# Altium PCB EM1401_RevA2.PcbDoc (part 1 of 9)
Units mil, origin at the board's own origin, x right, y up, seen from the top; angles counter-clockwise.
Board outline 7800 x 5300 mil, 6 copper layers (Top Layer, MidLayer1, MidLayer2, MidLayer3, MidLayer4, Bottom Layer), stack 16.8 mil thick; 751 components, 531 nets, 2554 pads, 1388 vias.
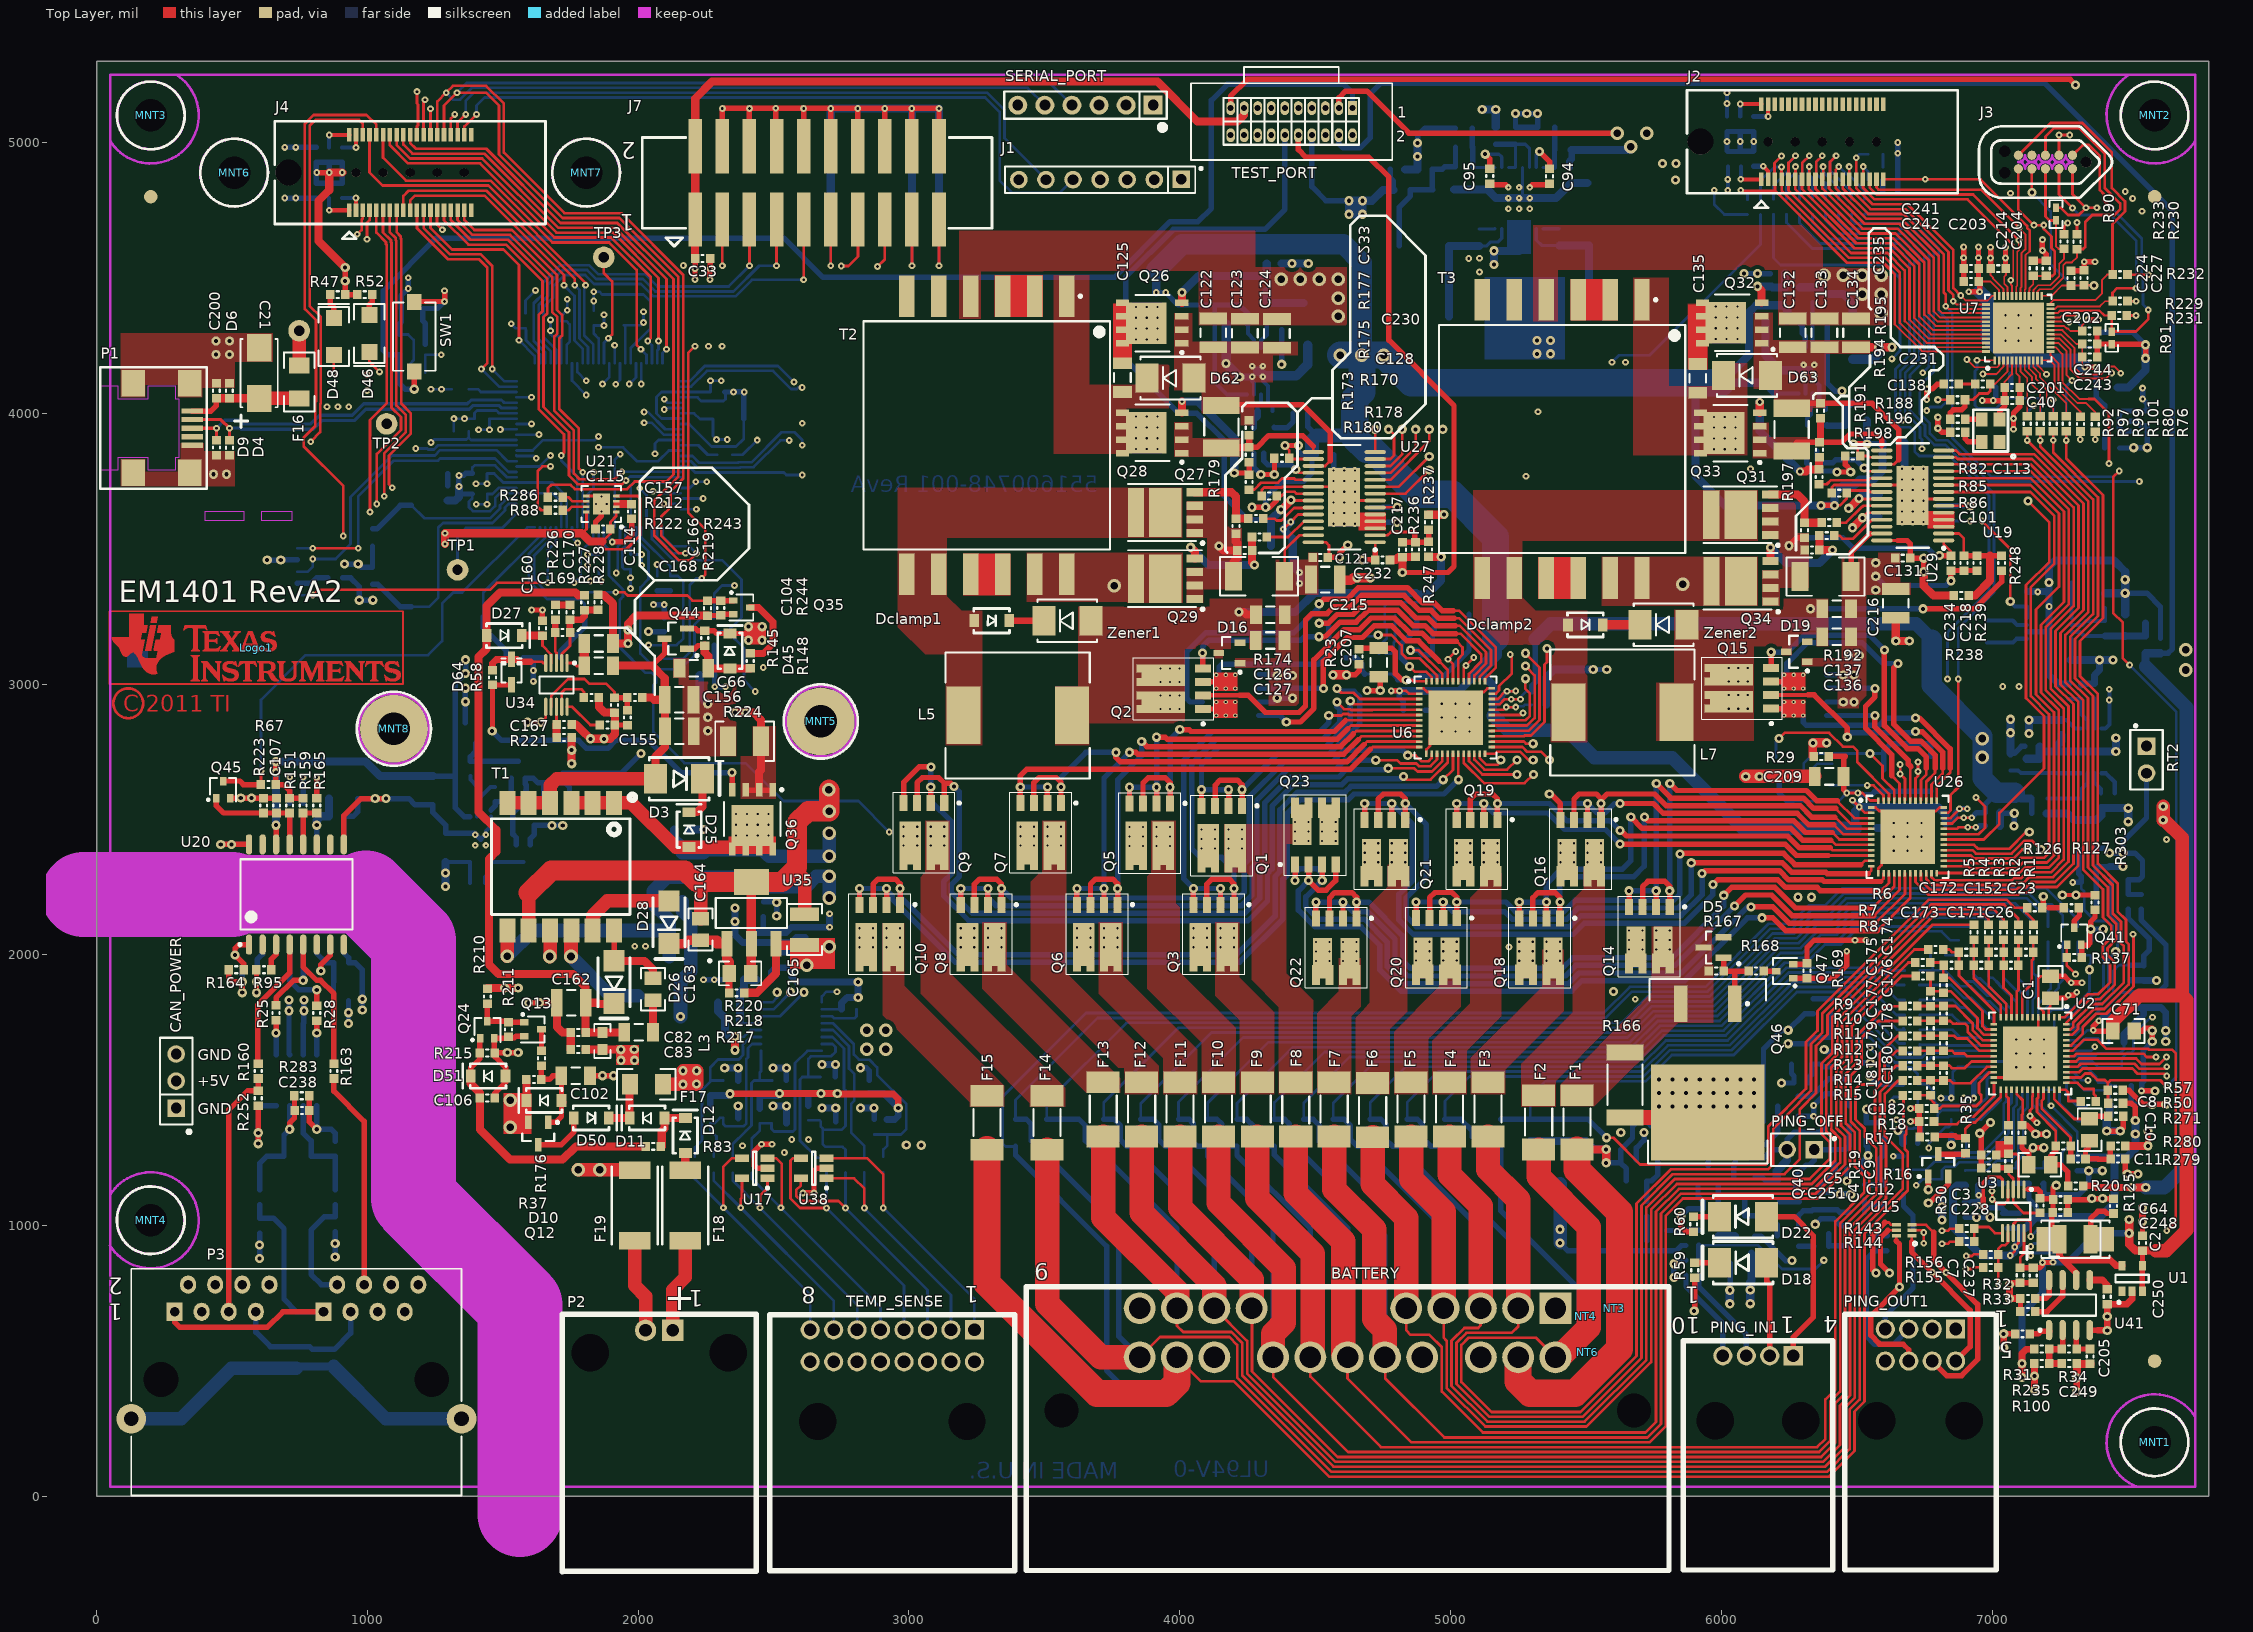
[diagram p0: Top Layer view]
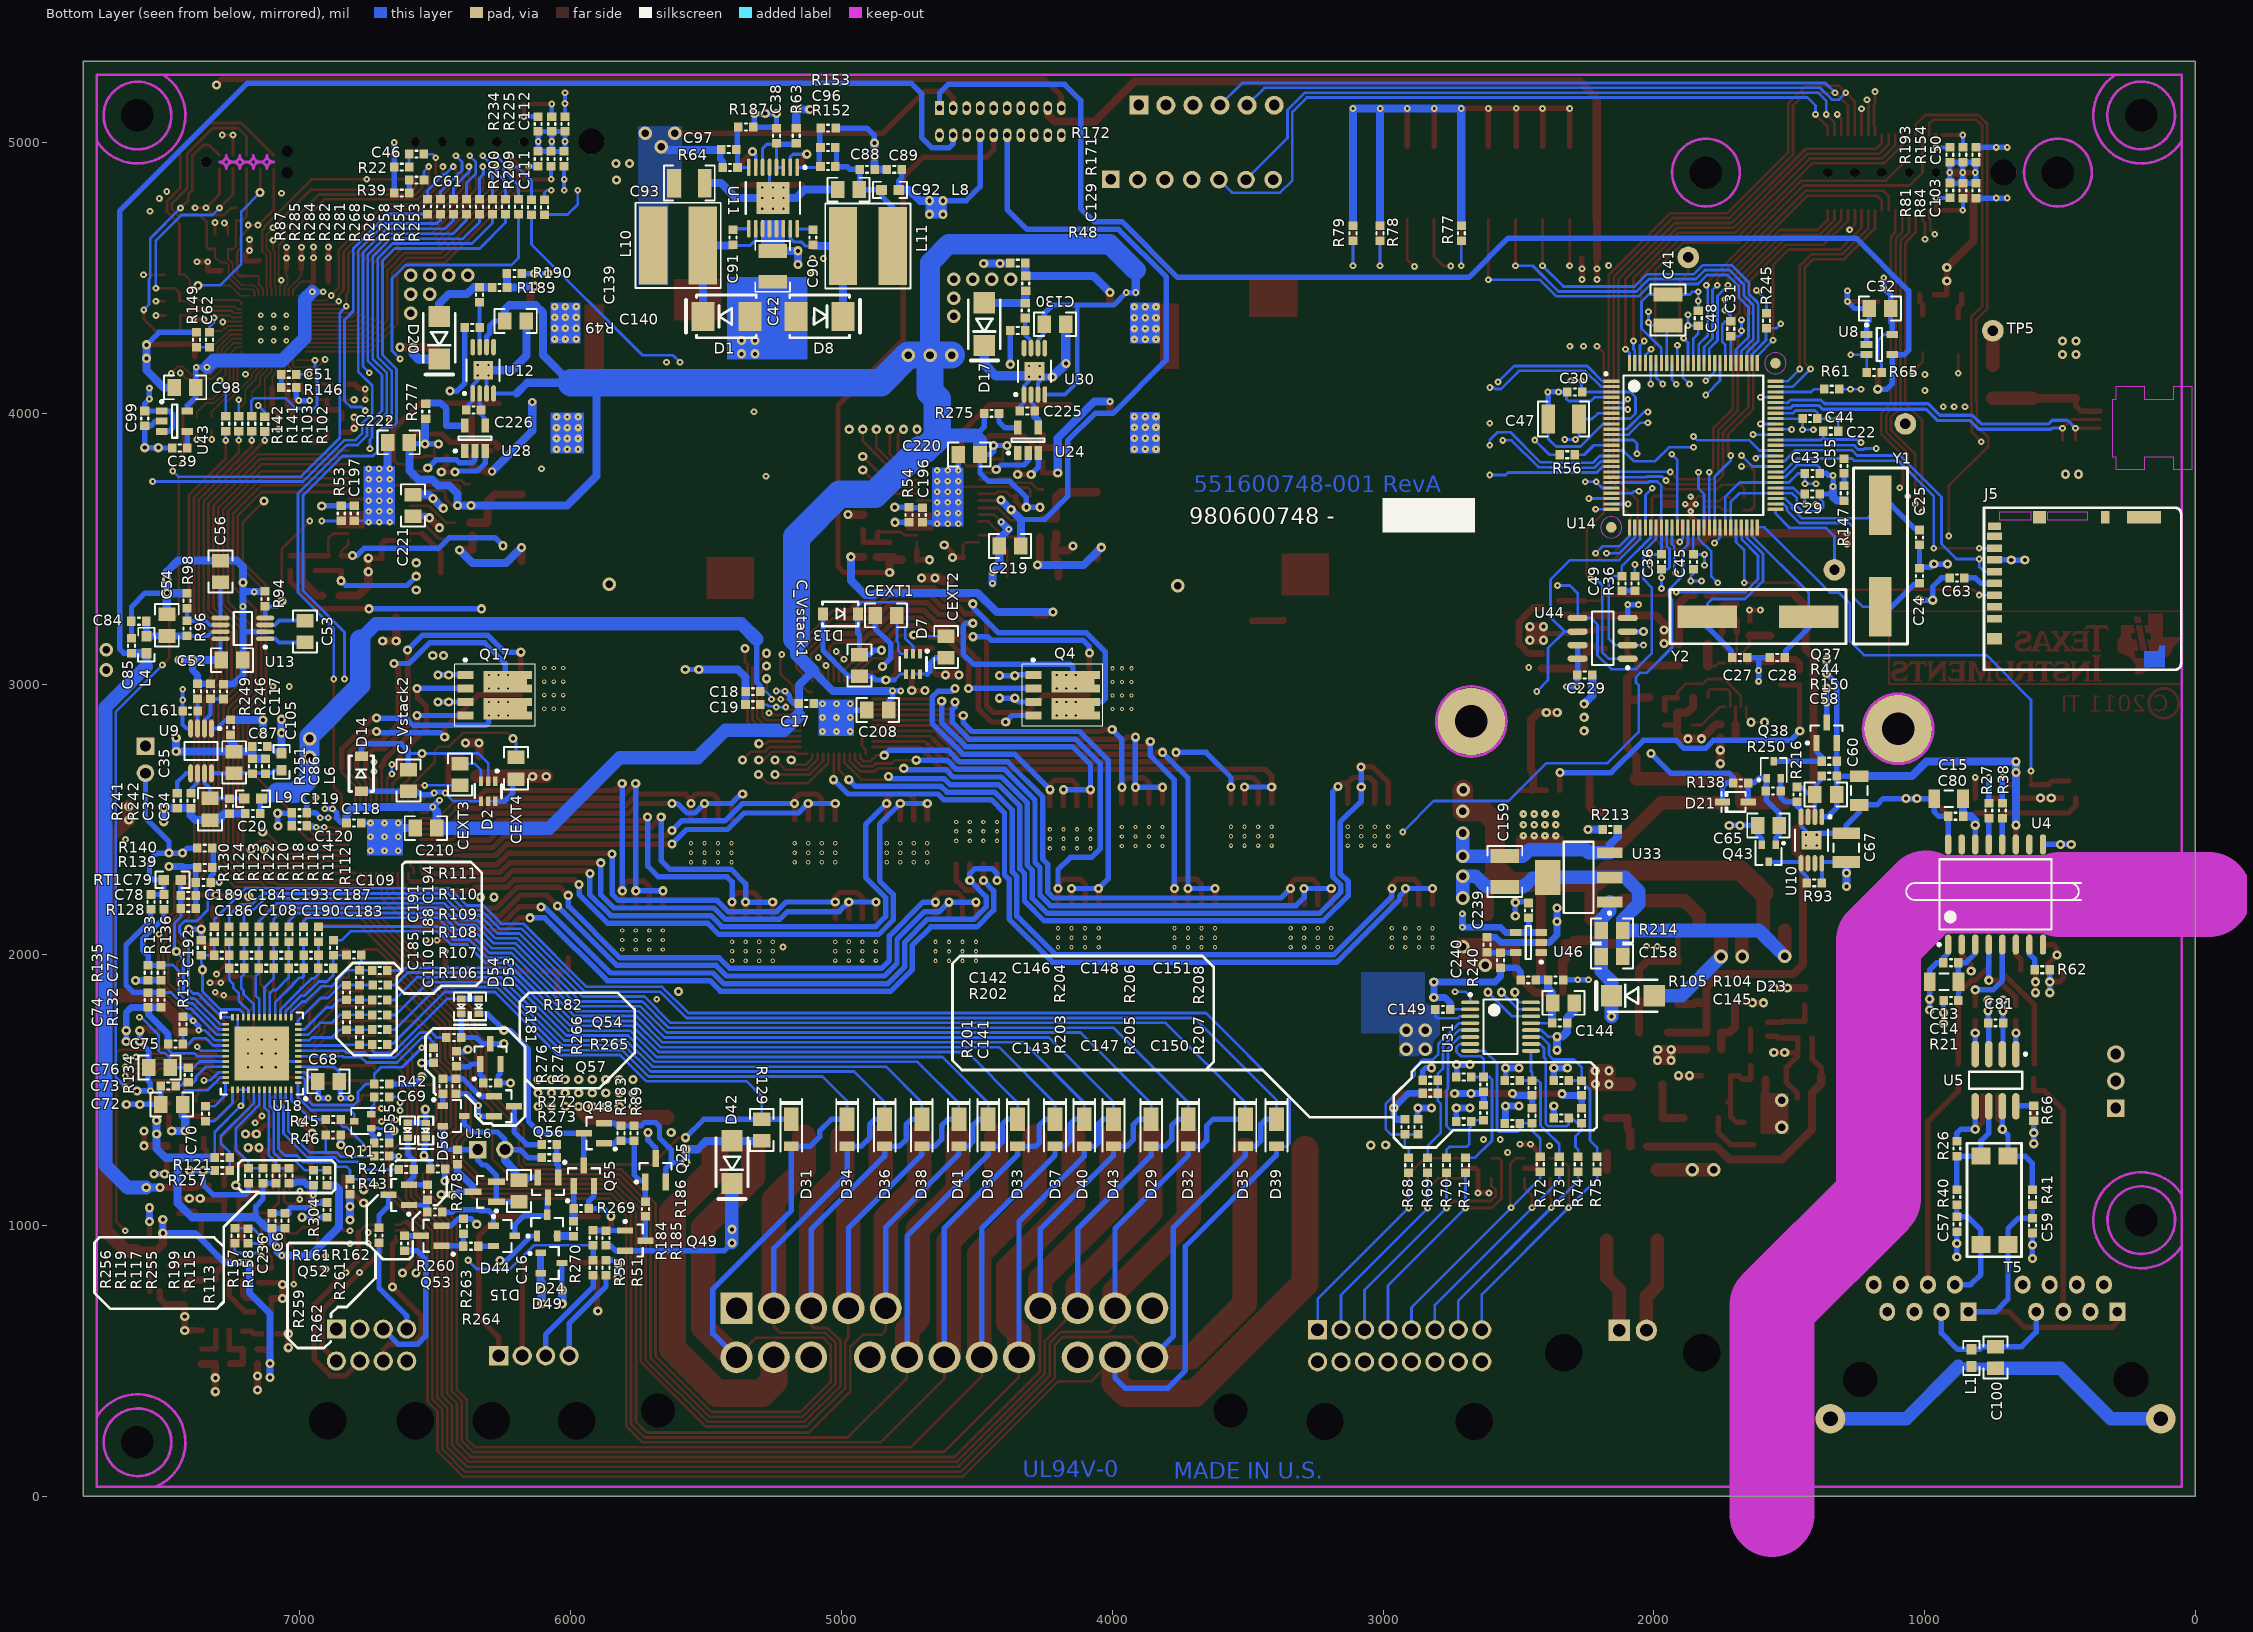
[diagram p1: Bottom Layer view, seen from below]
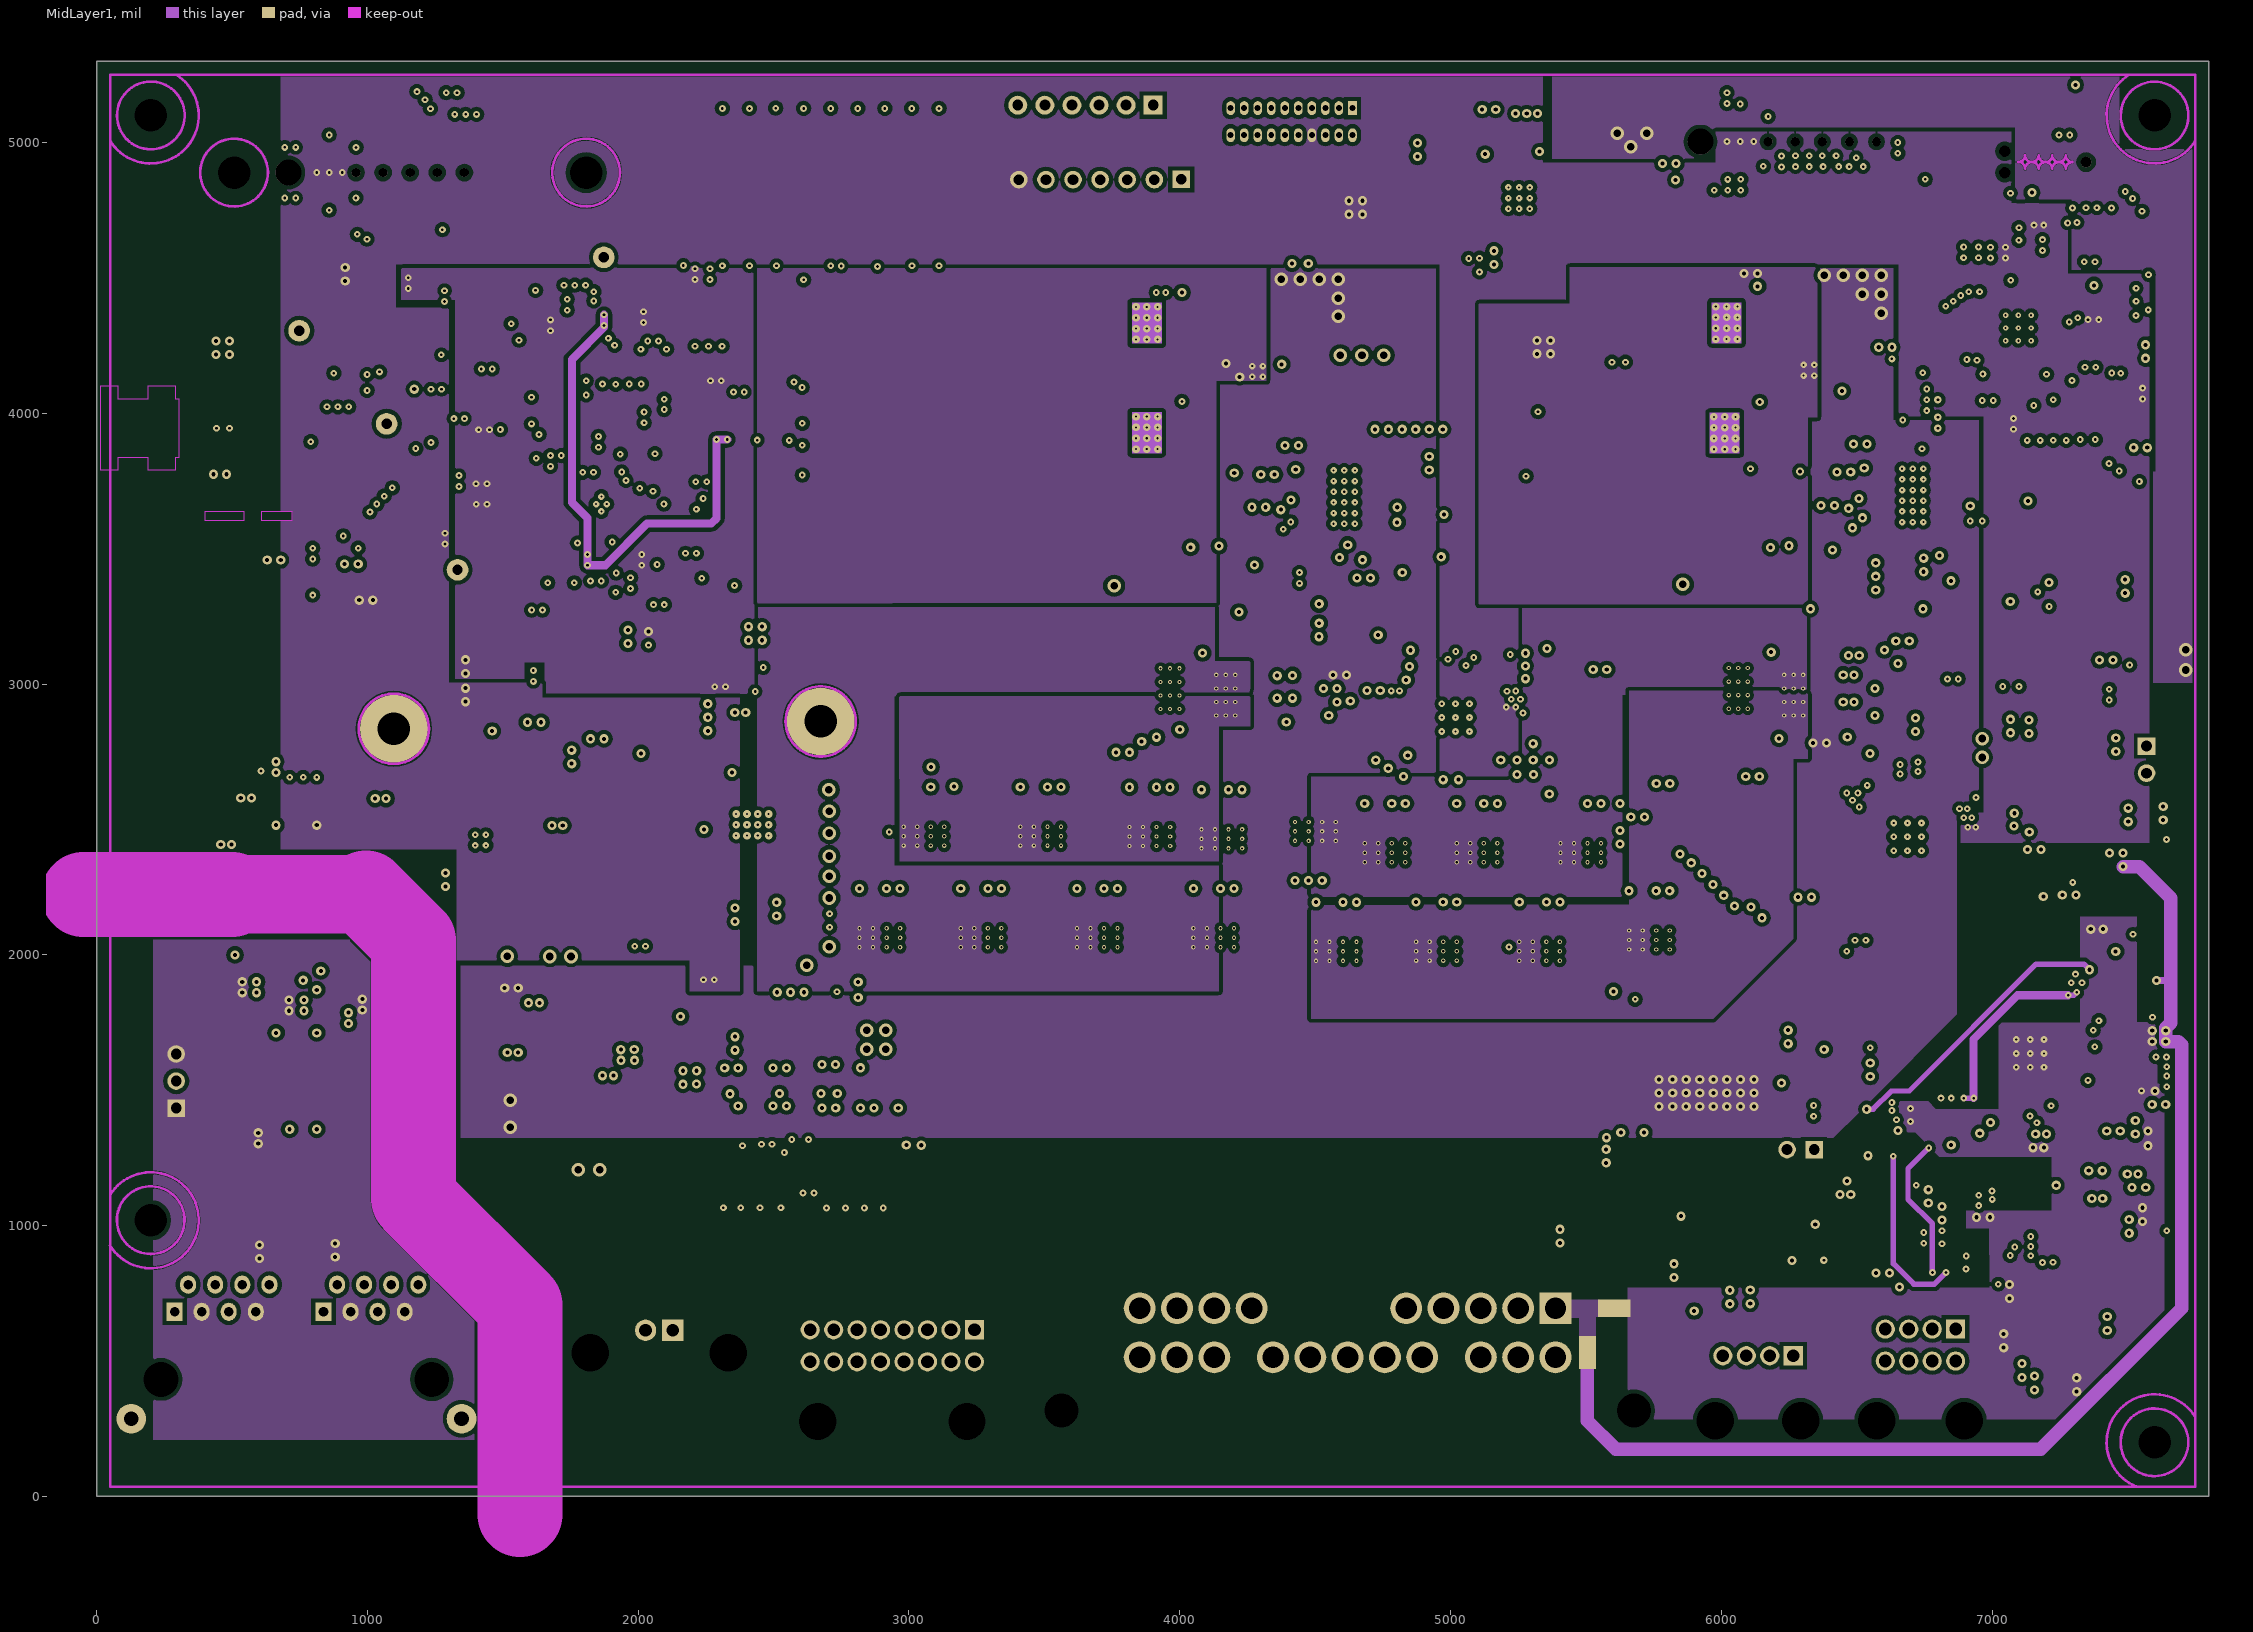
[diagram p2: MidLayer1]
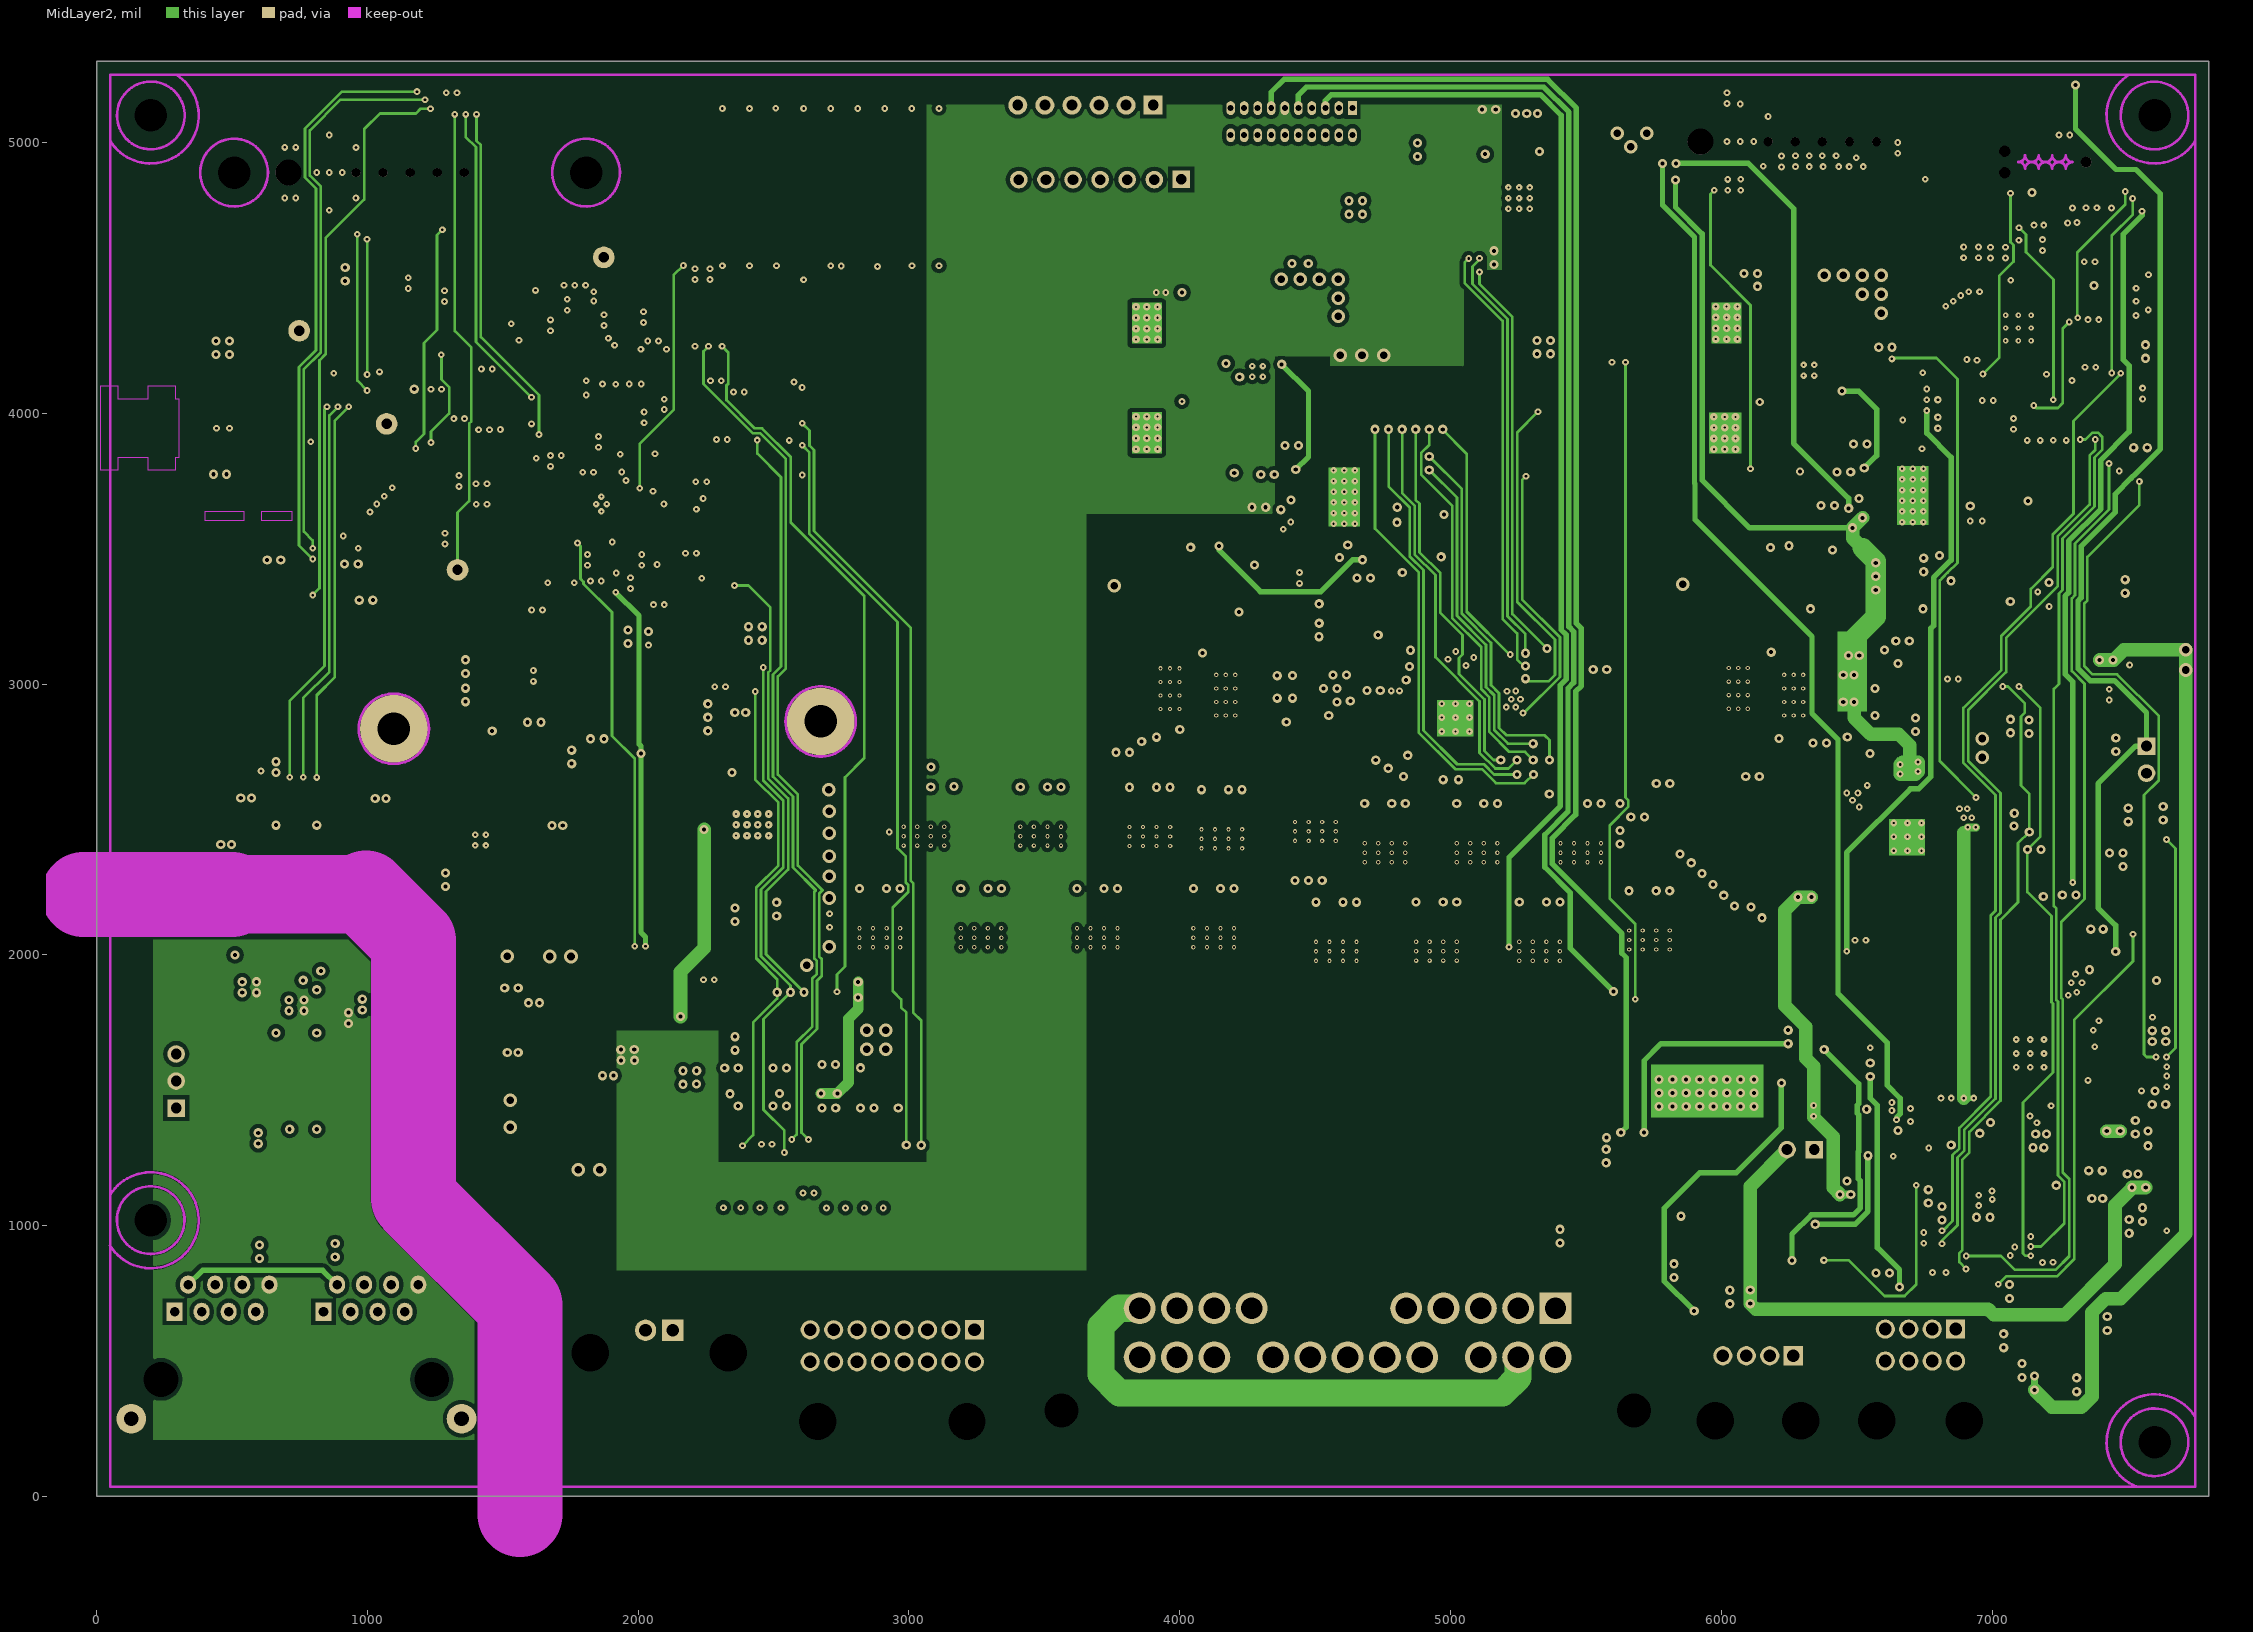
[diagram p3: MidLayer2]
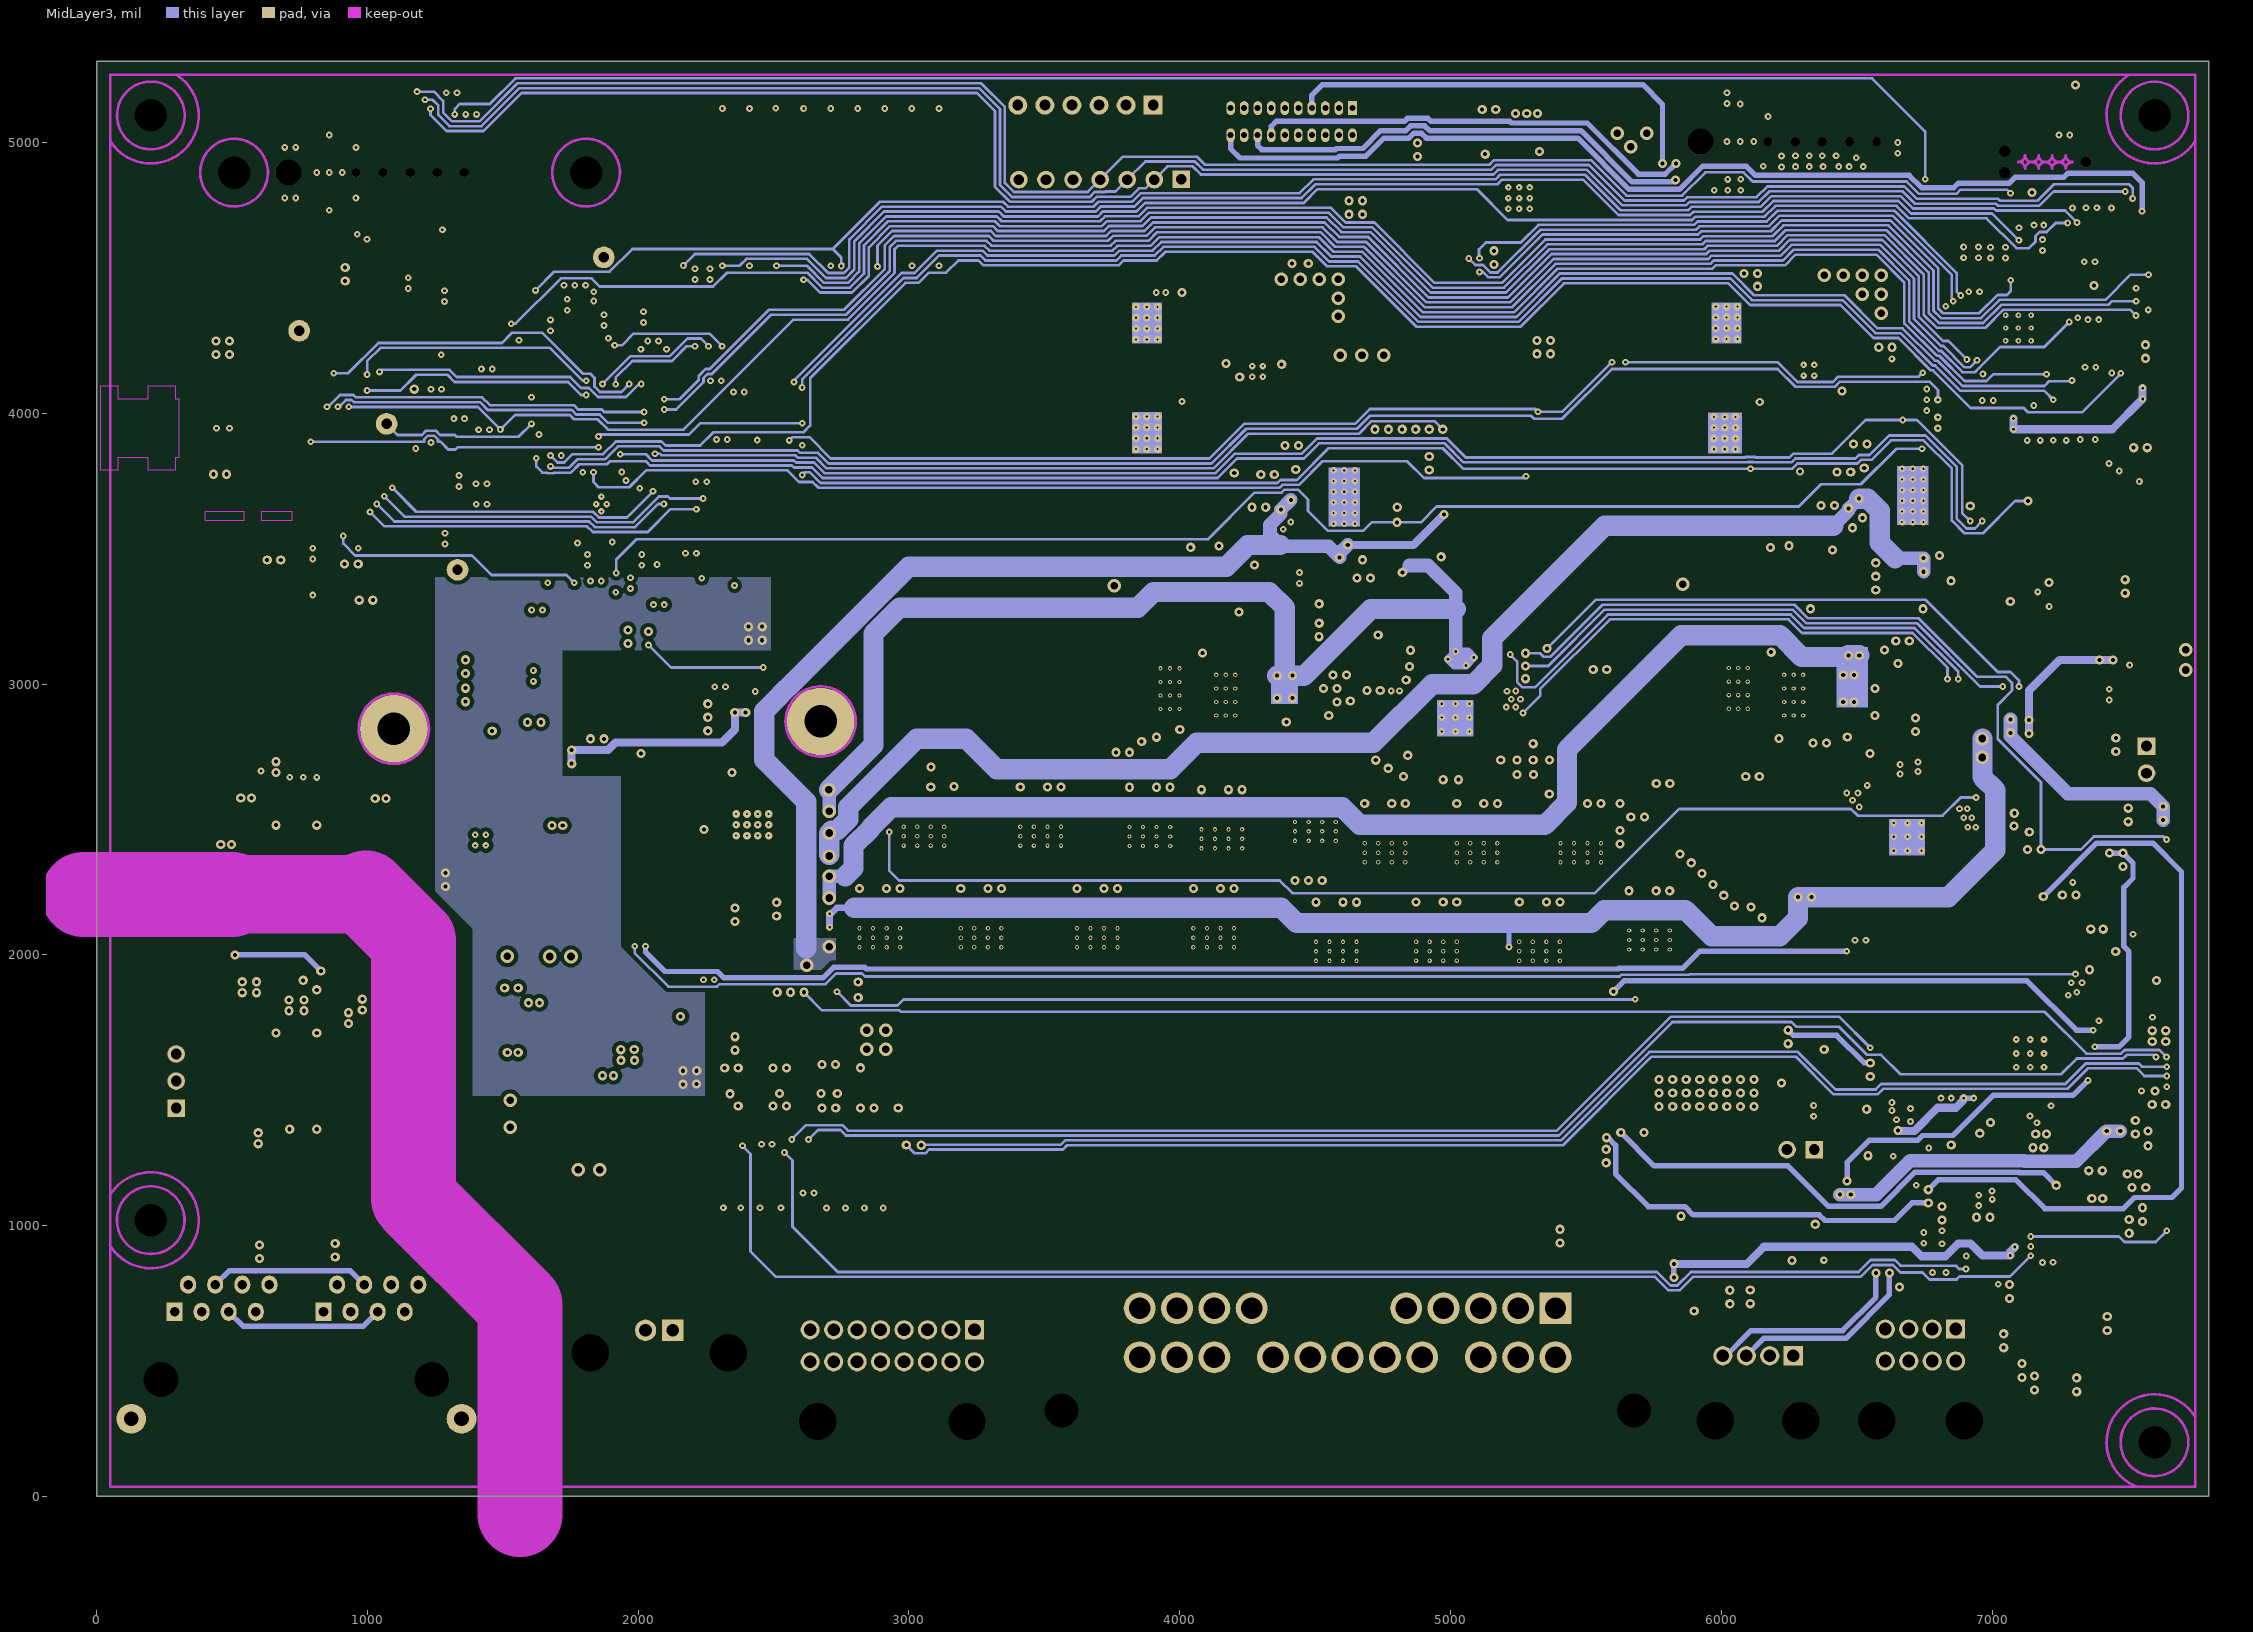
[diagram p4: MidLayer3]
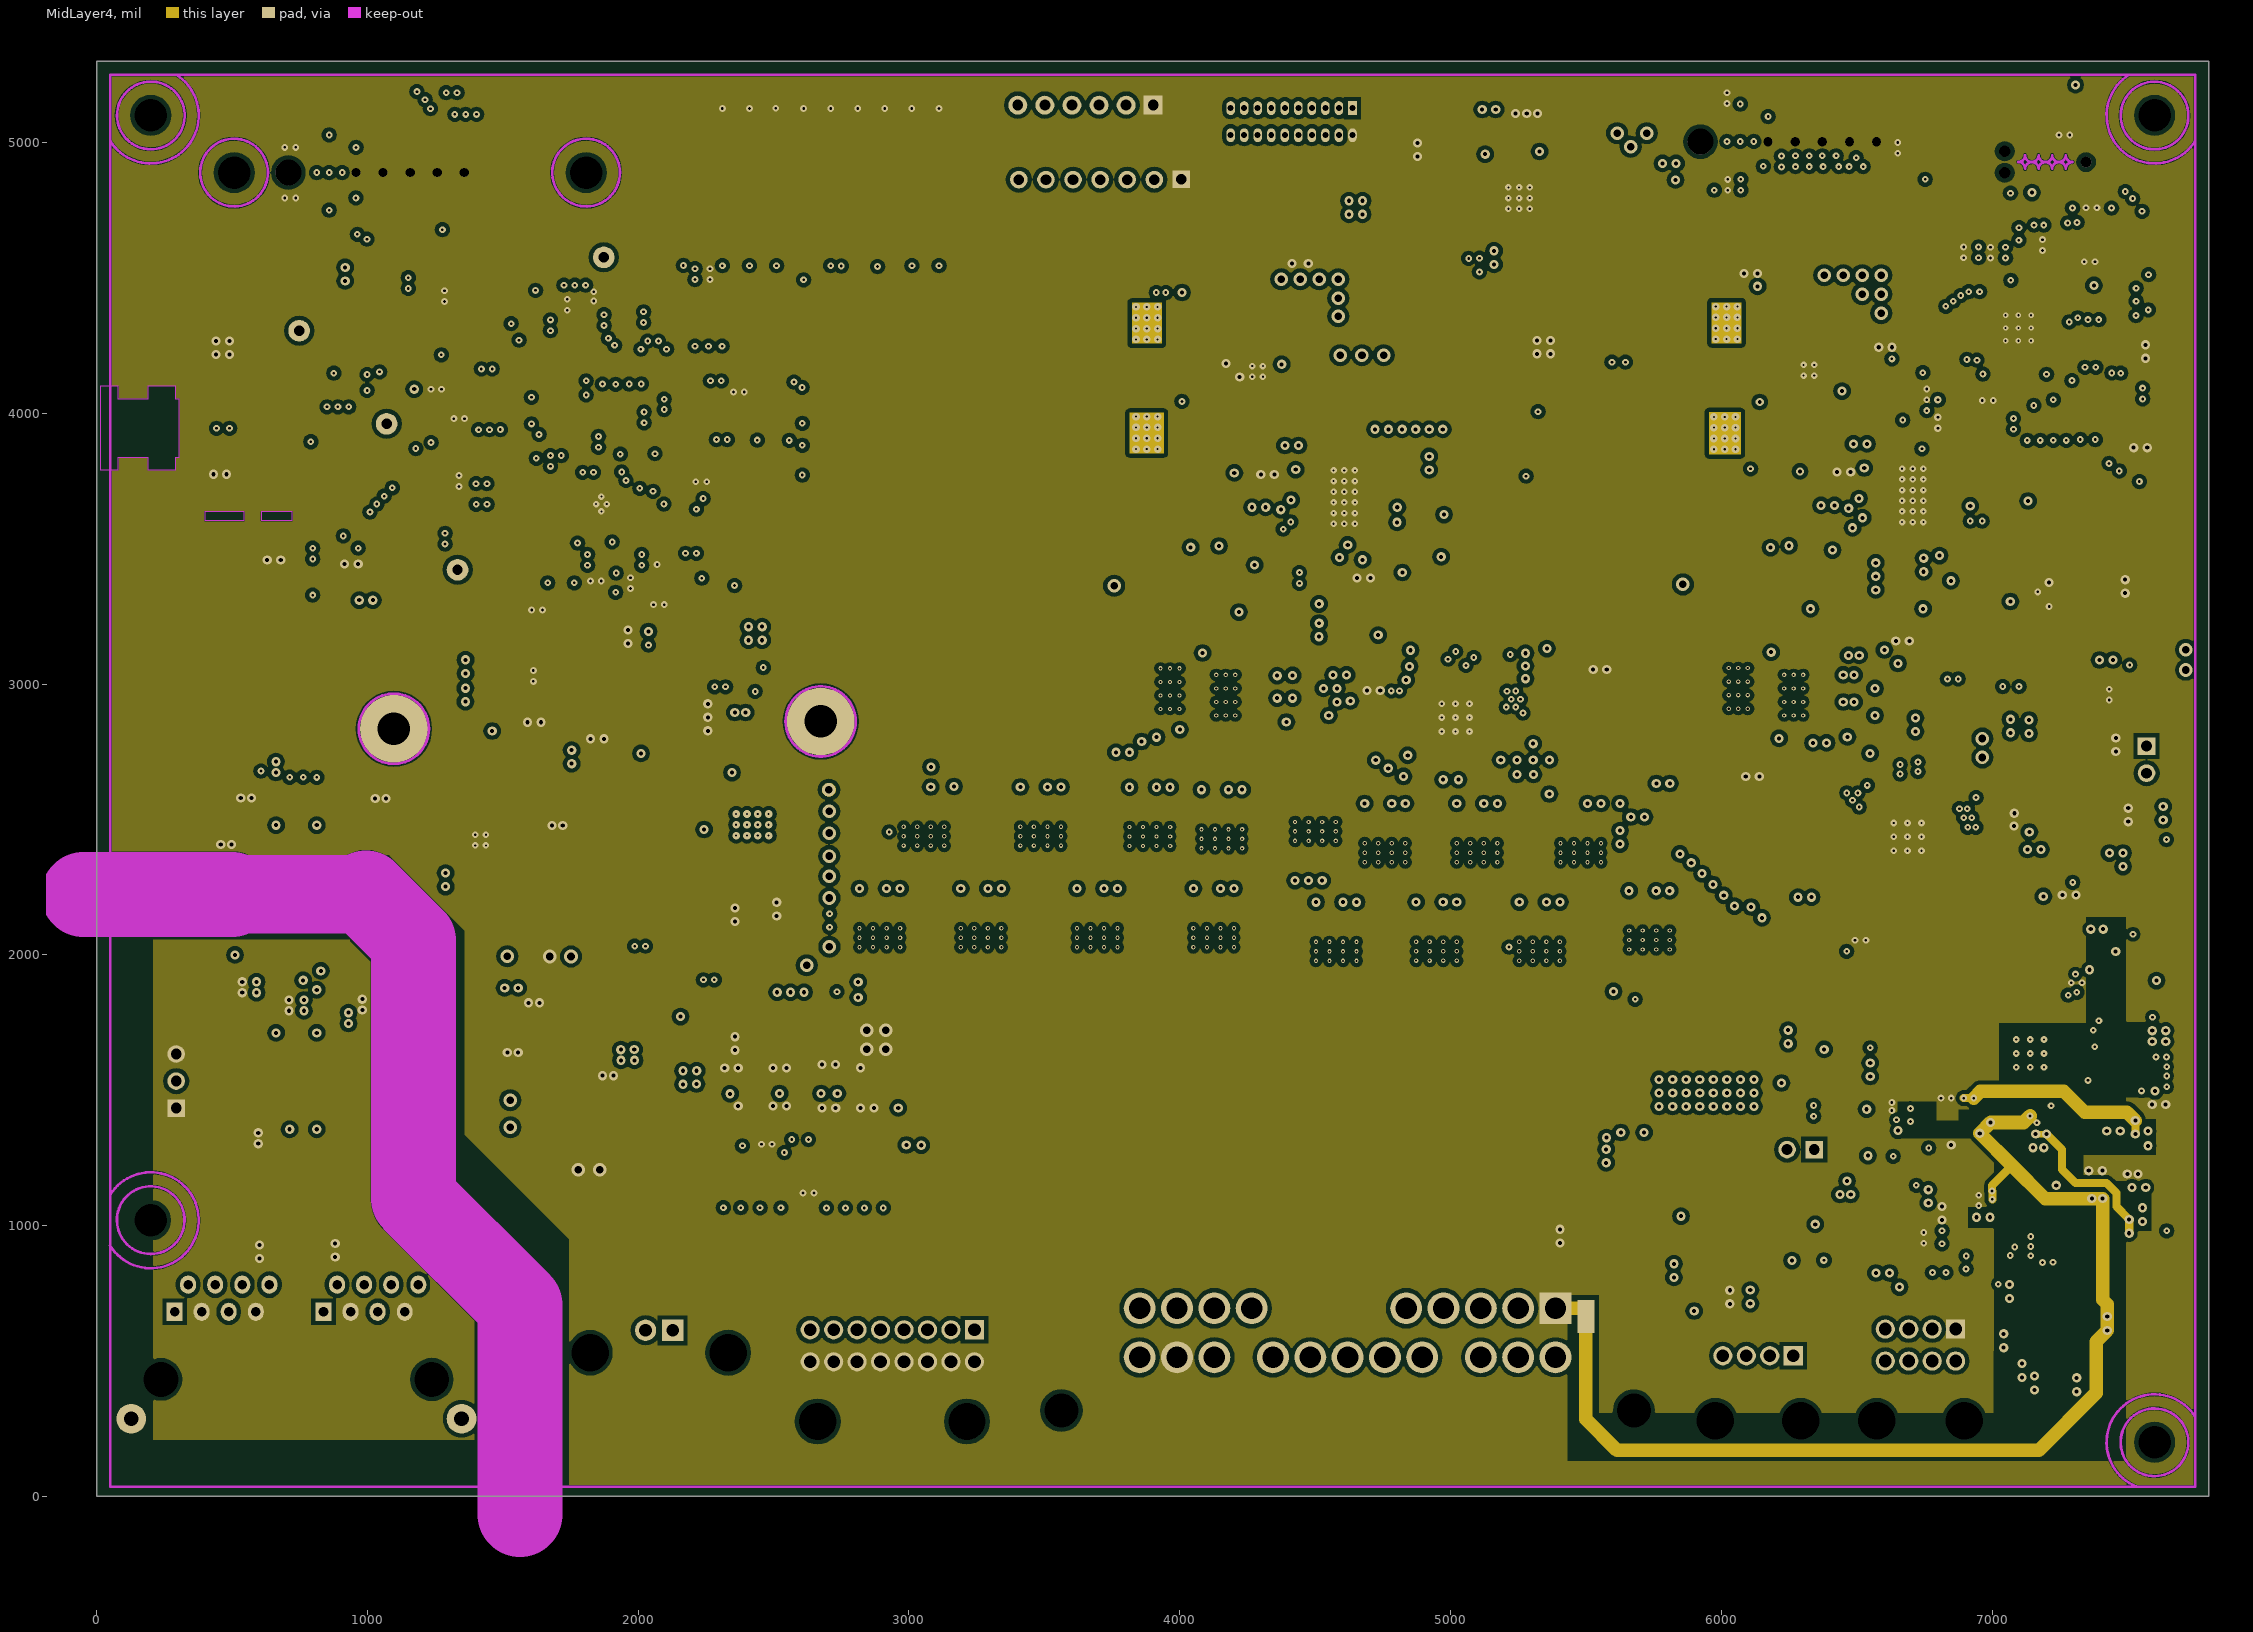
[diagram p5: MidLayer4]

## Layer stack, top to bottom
Top Layer: signal copper 2.8
MidLayer1: signal copper 2.8
MidLayer2: signal copper 2.8
MidLayer3: signal copper 2.8
MidLayer4: signal copper 2.8
Bottom Layer: signal copper 2.8

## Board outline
0,0 0,5300 7800,5300 7800,0

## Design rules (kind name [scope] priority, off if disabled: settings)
AssemblyTestpoint [(IsPad And (OnTopLayer Or OnBottomLayer)) Or (IsVia)] p1: testpointundercomponent=FALSE minsize=30 maxsize=60 preferedsize=34 minholesize=0 maxholesize=30 preferedholesize=15 testpointgrid=1 usegrid=FALSE gridtolerance=0.01 allowsidetop=TRUE allowsidebottom=TRUE minspacing=53 compbodyclearance=20 boardedgeclearance=25
Clearance "Keepout Clearance" [OnLayer('Keep-Out Layer')] p1: gap=2
Clearance "Polygon pours" [(IsRegion)] p2: gap=15
Clearance "fine pitch parts" [(HasFootprint('MUY08A_N') OR HasFootprint('MUA08A_N') OR HasFootprint('MSOP-10') OR HasFootprint('VEC64A_M') OR HasFootprint('MUA08A_L') OR HasFootprint('SQA20A') OR HasFootprint('LLP-8') OR HasFootprint('MUB10A_M') OR HasFootprint('MUB10A_N')OR HasFootprint('PVQFN14')OR HasFootprint ('QFP50P1600X1600X160-100N') OR HasFootprint ('QN48_N')OR HasFootprint ('SDA08A'))] p3: gap=5
Clearance [All] p4: gap=8
ComponentClearance "wavesolder wall clearance" [(InComponent('BATTERY') AND InComponent('P5') AND InComponent('P6') AND InComponent('TEMP_SENSE') AND InComponent('TEST_PORT') AND InComponent('T1') AND InComponent('T4') AND InComponent('PING_IN') AND InComponent('PING_OUT') AND InComponent('CAN1') AND InComponent('CAN2'))] p1: gap=250 collisioncheckmode=3 verticalgap=10 showdistances=FALSE
ComponentClearance [All] p2: gap=10 collisioncheckmode=3 verticalgap=0 showdistances=TRUE
DiffPairsRouting DiffPairsRouting_1 [All] p2: maxlimit=10 minlimit=10 mostfreqgap=10 maxuncoupledlength=500
FabricationTestPointUsage TestPointUsage [All] p1: valid=0 allowmultiple=TRUE
FabricationTestpoint Testpoint [All] p1: side=3 testpointundercomponent=FALSE minsize=30 maxsize=60 preferedsize=34 minholesize=12 maxholesize=30 preferedholesize=15 testpointgrid=5 allowsidetop=TRUE allowsidebottom=TRUE usegrid=FALSE gridtolerance=0.01 minspacing=50 compbodyclearance=50 boardedgeclearance=25
FanoutControl Fanout_LCC [IsLCC] p1: bgadir=Out bgaviamode=Centered fanoutstyle=Auto fanoutdirection=Alternating viagrid=1 // Fanout_LCC (Default Rule)
FanoutControl Fanout_BGA [IsBGA] p2: bgadir=Out bgaviamode=Centered fanoutstyle=Auto fanoutdirection=Alternating viagrid=1 // Fanout_BGA (Default Rule)
FanoutControl Fanout_Default [All] p4: bgadir=Out bgaviamode=Centered fanoutstyle=Auto fanoutdirection=Alternating viagrid=1 // Fanout_Default (Default Rule)
FanoutControl Fanout_Small [(CompPinCount < 5)] p5: bgadir=Out bgaviamode=Centered fanoutstyle=Auto fanoutdirection=OutThenIn viagrid=1 // Fanout_Small (Default Rule)
FanoutControl Fanout_BGA_1 [IsBGA] p6: bgadir=Out bgaviamode=Centered fanoutstyle=Auto fanoutdirection=Alternating viagrid=1 // Fanout_BGA (Default Rule)
FanoutControl Fanout_LCC_1 [IsLCC] p7: bgadir=Out bgaviamode=Centered fanoutstyle=Auto fanoutdirection=Alternating viagrid=1 // Fanout_LCC (Default Rule)
FanoutControl Fanout_SOIC_1 [IsSOIC] p8: bgadir=Out bgaviamode=Centered fanoutstyle=Auto fanoutdirection=Alternating viagrid=1 // Fanout_SOIC (Default Rule)
FanoutControl Fanout_Small_1 [(CompPinCount < 5)] p9: bgadir=Out bgaviamode=Centered fanoutstyle=Auto fanoutdirection=OutThenIn viagrid=1 // Fanout_Small (Default Rule)
FanoutControl Fanout_Default_1 [All] p10: bgadir=Out bgaviamode=Centered fanoutstyle=Auto fanoutdirection=Alternating viagrid=1 // Fanout_Default (Default Rule)
Height Height_1 [All] p2: minheight=0 maxheight=1000 prefheight=500
HoleSize [All] p1: absolutevalues=TRUE maxlimit=251 minlimit=8 maxpercent=80.000 minpercent=20.000
HoleToHoleClearance "DAP connections" [(HasFootprint('MXA14A_L'))] p1: gap=8 allowstackedmicrovias=TRUE
HoleToHoleClearance [All] p2: gap=10 allowstackedmicrovias=TRUE
LayerPairs LayerPairs_1 [All] p2: enforce=TRUE
MinimumAnnularRing "DAP vias" [(HasFootprint('MXA16A_N')OR Hasfootprint('MUY08A_N')OR HasFootprint('POWERPAK SO-8 -DUAL')OR HasFootprint('MXA14A_L')OR HasFootprint('MXA28A_M')OR HasFootprint('QN48_N'))] p1: minimumring=4
MinimumAnnularRing "TESTPORT connector" [(HasFootprint('5-104068-1'))] p2: minimumring=1
MinimumAnnularRing "AMP Connector" [(InComponent('PING') OR InComponent('TEMP_SENSE'))] p3: minimumring=6
MinimumAnnularRing [All] p4: minimumring=7.5
MinimumSolderMaskSliver "Footrprint Pads" [(HasFootprint('M08A_L') OR HasFootprint('SQA48B') OR HasFootprint('SQA48A') OR HasFootprint('SOIC16 Wide') OR HasFootprint('MXA28A_M') OR HasFootprint('M08A_N') OR HasFootprint('M14B_N') OR HasFootprint('mtc28_L') OR HasFootprint('MTC16_N') OR HasFootprint('MUA08A_N') OR HasFootprint('MUB10A_N') OR HasFootprint('MUY08A_N') OR HasFootprint('VEC64A_M')OR HasFootprint('MF05A_N')OR HasFootprint('MF05A_M')OR HasFootprint('MF05A_L')OR HasFootprint('MF06A_N')OR HasFootprint('PVQFN14')OR HasFootprint('UX60A-MB-5ST')OR HasFootprint('5767096-8')OR HasFootprint('QN48_N')OR HasFootprint('MXA16A_N')OR HasFootprint('DM3BT-DSF-PEJS')OR HasFootprint ('QFP50P1600X1600X160-100N') OR HasFootprint ('SDA08A')OR HasFootprint ('SOT-363') OR HasFootprint ('SC-89') OR HasFootprint ('TI_Logo_CopperSolderMask_1p1_x_p275'))] p1: minsoldermaskwidth=1
MinimumSolderMaskSliver [All] p2: minsoldermaskwidth=7
PasteMaskExpansion PasteMaskExpansion_1 [All] p2: expansion=0
PlaneConnect [All] p1: planeconnectstyle=Relief reliefexpansion=10 reliefentries=4 reliefconductorwidth=8 reliefairgap=10
PolygonConnect [All] p1: connectstyle=Direct reliefconductorwidth=8 reliefentries=4 polygonreliefangle="90 Angle" airgapwidth=10
RoomDefinition Top_Level [InComponentClass('Top_Level')] p1: confinementstyle=ConfineIn formatcopy=TRUE lockcomponents=FALSE outline 7845,-45 8700,-45 8700,1426 7845,1426
RoomDefinition "Temp Sense" [InComponentClass('Temp Sense')] p2: confinementstyle=ConfineIn formatcopy=TRUE lockcomponents=FALSE outline -692,-1234 1308,-1234 1308,-234 -692,-234
RoomDefinition TOP_Converter [InComponentClass('TOP_Converter')] p3: confinementstyle=ConfineIn formatcopy=TRUE lockcomponents=FALSE outline -692,-1234 1308,-1234 1308,-234 -692,-234
RoomDefinition BOTTOM_Converter [InComponentClass('BOTTOM_Converter')] p4: confinementstyle=ConfineIn formatcopy=TRUE lockcomponents=FALSE outline -692,-1234 1308,-1234 1308,-234 -692,-234
RoomDefinition VR [InComponentClass('VR')] p5: confinementstyle=ConfineIn formatcopy=TRUE lockcomponents=FALSE outline 9045,4217 12037,4217 12037,4688 9045,4688
RoomDefinition uController [InComponentClass('uController')] p6: confinementstyle=ConfineIn formatcopy=TRUE lockcomponents=FALSE outline 18222,3511 32234,3511 32234,10792 18222,10792
RoomDefinition "Top Half Stack" [InComponentClass('Top Half Stack')] p7: confinementstyle=ConfineIn formatcopy=TRUE lockcomponents=FALSE outline -692,-1234 1308,-1234 1308,-234 -692,-234
RoomDefinition FPGA [InComponentClass('FPGA')] p8: confinementstyle=ConfineIn formatcopy=TRUE lockcomponents=FALSE outline 9045,1487 9966,1487 9966,1753 9045,1753
RoomDefinition Engine [InComponentClass('Engine')] p9: confinementstyle=ConfineIn formatcopy=TRUE lockcomponents=FALSE outline -692,-1234 1308,-1234 1308,-234 -692,-234
RoomDefinition COMS [InComponentClass('COMS')] p10: confinementstyle=ConfineIn formatcopy=TRUE lockcomponents=FALSE outline 9045,850 14680,850 14680,1437 9045,1437
RoomDefinition BSP [InComponentClass('BSP')] p11: confinementstyle=ConfineIn formatcopy=TRUE lockcomponents=FALSE outline 6954.89,-354.62 6954.89,594.28 7183.79,594.28 7183.79,836.64 7236.36,836.64 7236.36,943.77 7261.15,943.77 7261.15,1462.5 7864.67,1462.5 7864.67,1623.29 7866.67,1623.29 7866.67,1677.29 7968.36,1677.29 7968.36,1677.31 8016.36,1677.31 8016.36,1732.31 8022.97,1732.31 8022.97,4250.04 17788.06,4250.04 17788.06,4626.98 17935.94,4626.98 17935.94,3480.21 18389.64,3480.21 18389.64,3373.74 19006.87,3373.74 19006.87,3172.48 17135.87,3172.48 17135.87,654.26 10113.55,654.26 10113.55,277.26 9127.77,277.26 9127.77,143.8 8185.94,143.8 8185.94,-343.46 7546.07,-343.46 7546.07,-354.62
RoomDefinition "Bottom Half Stack" [InComponentClass('Bottom Half Stack')] p12: confinementstyle=ConfineIn formatcopy=TRUE lockcomponents=FALSE outline -692,-1234 1308,-1234 1308,-234 -692,-234
RoomDefinition AFE [InComponentClass('AFE')] p13: confinementstyle=ConfineIn formatcopy=TRUE lockcomponents=FALSE outline 9045,56 11227,56 11227,327 9045,327
RoutingLayers [All] p1: top layer_v5=TRUE mid layer 2_v5=FALSE mid layer 4_v5=FALSE mid layer 5_v5=FALSE mid layer 7_v5=FALSE bottom layer_v5=TRUE
RoutingPriority RoutingPriority_1 [All] p2: routingpriority=0
RoutingTopology RoutingTopology_1 [All] p2: topology=Shortest
RoutingVias [All] p1: holewidth=16 width=32 viastyle="Through Hole" minholewidth=10 minwidth=25 maxholewidth=30 maxwidth=75
ShortCircuit "PGDNF to GNDF3" [InNet('PGNDF') vs InNet('GNDF3')] p1: allowed=TRUE
ShortCircuit "BAT0 to RGND" [InNet('BAT0') vs InNet('RGND')] p2: allowed=TRUE
ShortCircuit "RGND_BSP to BSP" [InNet('BAT0') vs InNet('RGND_BSP')] p3: allowed=TRUE
ShortCircuit "AGND to BAT0" [InNet('AGND') vs InNet('BAT0')] p4: allowed=TRUE
ShortCircuit [All] p5: allowed=FALSE
SilkToSilkClearance [All] p1: silktosilkclearance=7
SilkscreenOverComponentPads "0603L silk clearance" [(HasFootprint('0603L'))] p1: minsilkscreentomaskgap=3.5
SilkscreenOverComponentPads "50mil amp connectors" [(HasFootprint('5-104069-1') OR HasFootprint('5-104074-7') OR HasFootprint('5-104074-8'))] p2: minsilkscreentomaskgap=2.5
SilkscreenOverComponentPads "SOD123 diode" [(HasFootprint('SOD123 Flat Lead'))] p3: minsilkscreentomaskgap=3
SilkscreenOverComponentPads [All] p4: minsilkscreentomaskgap=4
SolderMaskExpansion [All] p1: expansion=3
UnRoutedNet UnRoutedNet_1 [All] p2:
Width [All] p1: maxlimit=125 minlimit=2 preferedwidth=20
12 further rules are at their usual default settings.

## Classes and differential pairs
net class MUX_[3..0]: MUX_0 MUX_1 MUX_2 MUX_3
component class "Top Half Stack": C118 C119 C120 C209 C210 C_Vstack2 CEXT3 CEXT4 D2 D14 Q14 Q15 Q16 Q17 Q18 Q19 Q20 Q21 Q22 Q23 R29 U26
component class BOTTOM_Converter: C121 C122 C123 C124 C125 C126 C127 C128 C129 C130 C196 C215 C217 C219 C220 C225 C230 C232 C233 D16 D17 D62 Dclamp1 L5 Q26 Q27 Q28 Q29 R48 R54 R170 R171 R172 R173 R174 R175 R177 R178 R179 R180 R236 R237 R247 R275 T2 U24 U27 U30 Zener1
component class "Bottom Half Stack": C17 C18 C19 C207 C208 C_Vstack1 CEXT1 CEXT2 D7 D13 "D?_Bottom Half Stack" Q1 Q2 Q3 Q4 Q5 Q6 Q7 Q8 Q9 Q10 R23 "U0_Bottom Half Stack" "U1_Bottom Half Stack" "U2_Bottom Half Stack" "U3_Bottom Half Stack" U6
component class Engine: D5 D42 F1 F2 F3 F4 F5 F6 F7 F8 F9 F10 F11 F12 F13 F14 F15 Q46 Q47 R166 R167 R168 R169
component class BSP: C16 C68 C69 C70 C71 C72 C73 C74 C75 C76 C77 C78 C79 C108 C109 C110 C183 C184 C185 C186 C187 C188 C189 C190 C191 C192 C193 C194 D15 D18 D22 D24 D44 D49 D53 D54 D55 D56 NT5 NT6 PING_IN1 PING_OFF PING_OUT1 Q11 Q25 Q48 Q49 Q52 Q53 Q54 Q55 Q56 Q57 R24 R42 R43 R45 R46 R51 R55 R59 R60 R89 R106 R107 R108 R109 R110 R111 R112 R113 R114 R115 R116 R117 R118 R119 R120 R121 R122 R123 R124 R128 R130 R131 R132 R133 R134 R135 R136 R139 R140 R161 R162 R181 R182 R183 R184 R185 R186 R199 R255 R256 R257 R259 R260 R261 R262 R263 R264 R265 R266 R269 R270 R272 R273 R274 R276 R278 RT1 RT2 U15 U16 U18 U?
component class "Temp Sense": C141 C142 C143 C144 C145 C146 C147 C148 C149 C150 C151 C239 C240 R68 R69 R70 R71 R72 R73 R74 R75 R104 R105 R201 R202 R203 R204 R205 R206 R207 R208 R240 TEMP_SENSE U17 U31 U38 U46
component class TOP_Converter: C131 C132 C133 C134 C135 C136 C137 C138 C139 C140 C197 C216 C218 C221 C222 C226 C231 C234 C235 D19 D20 D63 Dclamp2 L7 Q31 Q32 Q33 Q34 R49 R53 R188 R189 R190 R191 R192 R194 R195 R196 R197 R198 R238 R239 R248 R277 T3 U12 U28 U29 Zener2
component class AFE: C1 C2 C3 C4 C5 C6 C7 C8 C9 C10 C11 C12 C23 C26 C64 C152 C171 C172 C173 C174 C175 C176 C177 C178 C179 C180 C181 C182 C205 C228 C236 C237 C248 C249 C250 C251 NT3 NT4 Q40 Q41 R1 R2 R3 R4 R5 R6 R7 R8 R9 R10 R11 R12 R13 R14 R15 R16 R17 R18 R19 R20 R30 R31 R32 R33 R34 R35 R50 R57 R100 R125 R126 R127 R137 R235 R271 R279 R280 R303 R304 U1 U2 U3 U41
net class BAT[0..14]: BAT0 BAT1 BAT2 BAT3 BAT4 BAT5 BAT6 BAT7 BAT8 BAT9 BAT10 BAT11 BAT12 BAT13 BAT14
component class Top_Level: BATTERY BATTERY_18 C100 D12 D29 D30 D31 D32 D33 D34 D35 D36 D37 D38 D39 D40 D41 D43 F18 F19 L1 Logo1 MNT1 MNT2 MNT3 MNT4 MNT5 P2 P3 P7 PING R92 R97 R99 R101 R102 R103 R129 R141 R142 R143 R144 R155 R156 R157 R158 TEST_PORT
component class FPGA: C39 C40 C98 C99 C101 C111 C112 C113 C201 C202 C203 C204 C214 C224 C227 C241 C242 C243 C244 J2 J3 R76 R80 R82 R85 R86 R87 R90 R91 R200 R209 R225 R229 R230 R231 R232 R233 R234 R253 R254 R258 R267 R268 R281 R282 R284 R285 U7 U19 U43
component class VR: C20 C34 C35 C37 C38 C42 C52 C53 C54 C56 C58 C60 C65 C66 C67 C82 C83 C84 C85 C86 C87 C88 C89 C90 C91 C92 C93 C94 C95 C96 C97 C102 C104 C105 C106 C117 C155 C156 C157 C158 C159 C160 C161 C162 C163 C164 C165 C166 C167 C168 C169 C170 D1 D3 D8 D10 D11 D21 D23 D25 D26 D27 D28 D45 D50 D51 D64 F17 L3 L4 L6 L8 L9 L10 L11 Q12 Q13 Q24 Q35 Q36 Q37 Q38 Q43 Q44 R37 R44 R58 R63 R64 R83 R93 R94 R96 R98 R138 R145 R148 R150 R152 R153 R176 R187 R210 R211 R212 R213 R214 R215 R216 R217 R218 R219 R220 R221 R222 R224 R226 R227 R228 R241 R242 R243 R244 R246 R249 R250 R251 T1 T4 U9 U10 U11 U13 U33 U34 U35
net class FPGA_MUX[3..0]: FPGA_MUX0 FPGA_MUX1 FPGA_MUX2 FPGA_MUX3
component class COMS: C13 C14 C15 C21 C57 C59 C80 C81 C107 C200 C238 CAN_POWER D4 D6 D9 F16 P1 Q45 R21 R25 R26 R27 R28 R38 R40 R41 R62 R66 R67 R95 R151 R159 R160 R163 R164 R165 R223 R252 R283 T5 TP5 U4 U5 U20
component class uController: C22 C24 C25 C27 C28 C29 C30 C31 C32 C33 C36 C41 C43 C44 C45 C46 C47 C48 C49 C50 C51 C55 C61 C62 C63 C103 C114 C115 C229 D46 D48 J1 J4 J5 J7 MNT6 MNT7 MNT8 R22 R36 R39 R47 R52 R56 R61 R65 R77 R78 R79 R81 R84 R88 R146 R147 R149 R154 R193 R245 R286 SERIAL_PORT SW1 TP1 TP2 TP3 U8 U14 U21 U44 Y1 Y2

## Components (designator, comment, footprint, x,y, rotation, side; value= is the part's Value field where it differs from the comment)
BATTERY "175785-1" 175785 5387.64,695 r270 top
C1 "C2012X7R1E105K" 0805_HV 7215.41,1880.66 r270 top
C2 "GRM188R71A225KE15D" 0603L 7555.42,935.56 r90 top
C3 "C1608X5R1C105K" 0603L 7252.63,1096 r0 top
C4 "GRM1885C1H470JA01D" 0603L 7061.42,1237.44 r270 top
C5 "C1608C0G1H222J" 0603L 6987.42,1261.44 r180 top
C6 "C1608X7R1C104K" 0603L 7055,1018.56 r90 bottom
C7 "C1608X7R1C104K" 0603L 7103.83,816.44 r270 top
C8 "C1608X7R1H103K" 0603L 7354.86,1458 r180 top
C9 "C1608X7R1C104K" 0603L 7110.41,1343.1 r270 top
C10 "C2012X7R1E105K" 0805_HV 7360.42,1354 r270 top
C11 "C1608X7R1C104K" 0603L 7317.41,1246.65 r0 top
C12 "C2012X7R1E105K" 0805_HV 7176.21,1224.99 r180 top
C13 "0603YC104JAT2A" 0603L 903,1971 r180 bottom
C14 "C3216X7R1C106M" 1206L 928.15,1901 r180 bottom
C15 "C3216X7R1C106M" 1206L 911.15,2577 r180 bottom
C16 "C2012X7R1E105K" 0805_HV 6191,1128 r270 bottom
C17 "C1608X7R1C104K" 0603L 5129.92,2928 r0 bottom
C18 "C1608X7R1C104K" 0603L 5326.86,2972 r180 bottom
C19 "C1608X7R1C104K" 0603L 5326.98,2924 r180 bottom
C20 "C1608X7R1C104K" 0603L 7173.56,2522 r180 bottom
C21 "TPSC475K035R0600" 6032-28 600,4148.5 r90 top
C22 "C1608X7R1C104K" 0603L 1346.29,3933.69 r180 bottom
C23 "C0603C225K9PACTU" 0603L 7124.91,2009.65 r180 top
C24 "C1608C0G1H100D" 0603L 1019,3399.5 r90 bottom
C25 "C1608C0G1H100D" 0603L 1019,3541.5 r270 bottom
C26 "C0603C225K9PACTU" 0603L 7069.91,1961.65 r180 top
C27 "C1608C0G1H100D" 0603L 1682.5,3098 r180 bottom
C28 "C1608C0G1H100D" 0603L 1544.5,3098 r0 bottom
C29 "C1608X7R1C104K" 0603L 1415,3702 r180 bottom
C30 "C1608X7R1C104K" 0603L 2291.56,4078.85 r0 bottom
C31 "C1608X7R1C104K" 0603L 1716,4312.56 r90 bottom
C32 "C2012X7R1C225K" 0805_HV 1165,4387 r0 bottom
C33 "C1608X7R1C104K" 0603L 2238,4572 r180 top
C34 "C1608X7R1C104K" 0603L 7260,2549.44 r90 bottom
C35 "C2012X7R1E105K" 0805_HV 7243,2711 r90 bottom
C36 "C1608X7R1C104K" 0603L 1972,3451.29 r270 bottom
C37 "C2012X7R1E105K" 0805_HV 7332,2538 r270 bottom
C38 "C1608X7R1C224K" 0603L 5240,5025.5 r270 bottom
C39 "GRM188R71C103KA01D" 0603L 7443.56,3872 r180 bottom
C40 "GRM188R71C103KA01D" 0603L 7074.44,4047 r0 top
C41 "GRM31MR71E225KA93L" 1210#1 1948,4382 r90 bottom
C42 "GRM32DR61E106KA12L" 1210#1 5254,4542.91 r270 bottom
C43 "GRM188R71E103KA01D" 0603L 1414.44,3778 r0 bottom
C44 "GRM188R71E103KA01D" 0603L 1423.29,3980.43 r0 bottom
C45 "C1608X7R1C104K" 0603L 1854,3451.29 r270 bottom
C46 "C1608C0G1H330J" 0603L 6569.44,4957 r180 bottom
C47 "GRM31MR71E225KA93L" 1210#1 2333.09,3979 r0 bottom
C48 "GRM188R71E103KA01D" 0603L 1836,4351.56 r270 bottom
C49 "C1608C0G1H330J" 0603L 2118,3371.44 r90 bottom
C50 "C1608X7R1C105K" 0603L 811,4954.56 r270 bottom
C51 "C1608C0G1H330J" 0603L 7041,4144 r0 bottom
C52 "C2012X7R1E105K" 0805_HV 7250.64,3088.57 r180 bottom
C53 "C2012X7R1E105K" 0805_HV 6981.57,3194.07 r90 bottom
C54 "C2012X7R1E105K" 0805_HV 7491.64,3217.57 r270 bottom
C55 "C1608C0G1H330J" 0603L 1297,3805.44 r270 bottom
C56 "C2012X7R1E105K" 0805_HV 7293.42,3416 r270 bottom
C57 "06035A220JAT2A" 0603L 881,1005.44 r90 bottom
C58 "GRM21BR72A103KA01L" 0805_HV 1365,2592 r0 bottom
C59 "06035A220JAT2A" 0603L 602,1000.44 r270 bottom
C60 "C3216X7R1C106M" 1206L 1242,2606.85 r270 bottom
C61 "C1608C0G1H330J" 0603L 6569.32,4861 r180 bottom
C62 "C1608C0G1H330J" 0603L 7334,4271.44 r270 bottom
C63 "C1608X7R1C104K" 0603L 880.44,3392 r180 bottom
C64 "GCM32ER70J476KE19L" 1210#2 7363.59,950 r180 top
C65 "C2012X7R1E105K" 0805_HV 1577,2478 r180 bottom
C66 "C3216X7R2A104K" 1206L 2205.85,3058 r0 top
C67 "GRM32ER71H475KA88L" 1210L 1289,2396.15 r90 bottom
C68 "C2012X7R1E105K" 0805_HV 6894.42,1533 r0 bottom
C69 "C1608X7R1C104K" 0603L 6698.44,1475 r180 bottom
C70 "C1608X7R1H103K" 0603L 7348.42,1413 r90 bottom
C71 "C2012X7R1E105K" 0805_HV 7485.41,1718.65 r0 top
C72 "C2012X7R1E105K" 0805_HV 7473.41,1447.65 r0 bottom
C73 "C1608X7R1C104K" 0603L 7485.97,1515.65 r180 bottom
C74 "C1608X7R1C104K" 0603L 7560.42,1833.44 r270 bottom
C75 "C1608X7R1C104K" 0603L 7459.42,1671 r0 bottom
C76 "C2012X7R1E105K" 0805_HV 7518.42,1584 r0 bottom
C77 "C1608X7R1C104K" 0603L 7512.42,1933.56 r270 bottom
C78 "C1608X7R1C104K" 0603L 7411.98,2220 r180 bottom
C79 "C1608X7R1C104K" 0603L 7356.51,2267.77 r0 bottom
C80 "0603YC104JAT2A" 0603L 885.56,2512 r180 bottom
C81 "C1608X7R1C104K" 0603L 738,1749 r0 bottom
C82 "C1608X7R1C104K" 0603L 1778.44,1713 r0 top
C83 "C1608X7R1C104K" 0603L 1778.56,1651 r0 top
C84 "C1608X7R1C104K" 0603L 7594.56,3232 r180 bottom
C85 "C1608X7R1C104K" 0603L 7622,3141.56 r270 bottom
C86 "C1608X7R1C104K" 0603L 7127,2696.56 r270 bottom
C87 "C1608X7R1C104K" 0603L 7148.56,2770 r180 bottom
C88 "C1608X7R1C104K" 0603L 4905.44,4901 r0 bottom
C89 "C1608X7R1C104K" 0603L 4805.35,4901 r180 bottom
C90 "C1608X7R1C104K" 0603L 5106,4649.5 r270 bottom
C91 "C1608X7R1C104K" 0603L 5401,4649.5 r90 bottom
C92 "JMK212BJ476MG-T" 0805_HV 4974,4826 r0 bottom
C93 "GRM32DR60J336ME19L" 1210#1 5562,4850 r180 bottom
C94 "GRM188R71C123KA01D" 0603L 5366,4875 r90 top
C95 "GRM188R71C123KA01D" 0603L 5145,4876 r90 top
C96 "GRM188R71E273KA01D" 0603L 5050,4982 r180 bottom
C97 "GRM188R71E273KA01D" 0603L 5416,4974 r180 bottom
C98 "C0805C475K8PACTU" 0805_HV 7424,4096 r0 bottom
C99 "C1608X7R1C105K" 0603L 7573,3981 r90 bottom
C100 "C2012X7R1E105K" 0805_HV 738,513 r270 bottom
C101 "GRM188R71C103KA01D" 0603L 6873.44,3930 r0 top
C102 "C3216X7R2A104K" 1206L 1769.15,1553 r180 top
C103 "C1608X7R1C105K" 0603L 811,4822.44 r90 bottom
C104 "C1608X7R1C104K" 0603L 2256,3280.44 r90 top
C105 "C1608X7R1C105K" 0603L 7257,2840 r270 bottom
C106 "C1608X7R1C104K" 0603L 1443,1472 r0 top
C107 "C1608X7R1C104K" 0603L 665,2551.56 r270 top
C108 "C0603C225K9PACTU" 0603L 7123.97,1950.65 r0 bottom
C109 "C0603C225K9PACTU" 0603L 6800.42,1999 r0 bottom
C110 "C0603C225K9PACTU" 0603L 6780.41,1696.1 r90 bottom
C111 "C1608X7R1C105K" 0603L 6024,4939.44 r90 bottom
C112 "C1608X7R1C105K" 0603L 6021,5068.44 r270 bottom
C113 "C1608C0G1H330J" 0603L 6965.56,4108 r0 top
C114 "GRM188R71C102KA01D" 0603L 1975,3637.44 r90 top
C115 "C1608X7R1C104K" 0603L 1870,3573 r0 top
C117 "C0603C331K5RACTU" 0603L 7282,2972.56 r270 bottom
C118 "C1608X7R1C104K" 0603L 6800.42,2487 r0 bottom
C119 "C1608X7R1C104K" 0603L 7001.85,2524.98 r180 bottom
C120 "C1608X7R1C104K" 0603L 7001.85,2476.98 r180 bottom
C121 "C1608X7R1C104K" 0603L 4519.42,3468 r180 top
C122 "GRM32ER72A225KA35L" 1210L 4123.92,4297 r270 top
C123 "GRM32ER72A225KA35L" 1210L 4240.92,4296 r270 top
C124 "GRM32ER72A225KA35L" 1210L 4358.92,4295 r270 top
C125 "12061C104KAT2A" 1206L 3788.42,4132 r90 top
C126 "GRM319R61A106KE19D" 1206L 4334.53,3256.46 r0 top
C127 "GRM319R61A106KE19D" 1206L 4333.92,3161 r0 top
C128 "C1608X7R1C104K" 0603L 4330.42,3695 r0 top
C129 "C1608X7R1C104K" 0603L 4321.42,4379.56 r270 bottom
C130 "C0805C225K4RACTU" 0805_HV 4211.42,4329 r180 bottom
C131 "C1608X7R1C104K" 0603L 6669.92,3465 r180 top
C132 "GRM32ER72A225KA35L" 1210L 6263.75,4297.16 r270 top
C133 "GRM32ER72A225KA35L" 1210L 6380.75,4297.16 r270 top
C134 "GRM32ER72A225KA35L" 1210L 6497.75,4297.16 r270 top
C135 "12061C104KAT2A" 1206L 5913.42,4129 r90 top
C136 "GRM319R61A106KE19D" 1206L 6426.17,3174.51 r0 top
C137 "GRM319R61A106KE19D" 1206L 6426.17,3278.51 r0 top
C138 "C1608X7R1C104K" 0603L 6435.42,3705 r0 top
C139 "C1608X7R1C104K" 0603L 6336.42,4438 r270 bottom
C140 "C0805C225K4RACTU" 0805_HV 6203.42,4341 r180 bottom
C141 "C1608X7R1E104K" 0603L 2871.42,1364.56 r90 bottom
C142 "C1608X7R1E104K" 0603L 2825.98,1537 r0 bottom
C143 "C1608X7R1E104K" 0603L 2701.98,1384 r0 bottom
C144 "C1608X7R1E104K" 0603L 2347.86,1748 r180 bottom
C145 "C0805C105K4RACTU" 0805_HV 2333.42,1823 r180 bottom
C146 "C1608X7R1E104K" 0603L 2701.98,1549 r0 bottom
C147 "C1608X7R1E104K" 0603L 2522.98,1378 r0 bottom
C148 "C1608X7R1E104K" 0603L 2522.86,1536 r0 bottom
C149 "C1608X5R1A105K" 0603L 2778.98,1799 r0 bottom
C150 "C1608X7R1E104K" 0603L 2341.86,1398 r0 bottom
C151 "C1608X7R1E104K" 0603L 2341.98,1536 r0 bottom
C152 "C0603C225K9PACTU" 0603L 7014.91,2009.65 r180 top
C155 "GRM32ER71H475KA88L" 1210L 2152.06,2825.49 r0 top
C156 "GRM32ER71H475KA88L" 1210L 2151.42,2942 r0 top
C157 "C3216X7R2A104K" 1206L 1854,3150 r180 top
C158 "C2012X7R1E105K" 0805_HV 2154.42,1994 r180 bottom
C159 "C3225X7R1C106M" 1210#1 2550.42,2308 r270 bottom
C160 "0.47, 16V" 0603L 1646.5,3206 r90 top
C161 "7V, 340pF" 0603L 7405.56,2900 r0 bottom
C162 "C3225X5R1C226M" 1210L 1752.85,1823 r180 top
C163 "CC0805JRNP09BN471" 0805_HV 2055,1873 r270 top
C164 "C2012X7R1E105K" 0805_HV 2230.42,2094 r90 top
C165 "C3225X7R1C106M" 1210#1 2614.42,2093.15 r90 top
C166 "GRM188R71E103KA01D" 0603L 1912.5,2922.44 r90 top
C167 "06035A102KAT2A" 0603L 1726.5,2851 r0 top
C168 "GRM188R71E103KA01D" 0603L 1886.5,2849 r180 top
C169 "06035A331JAT2A" 0603L 1721,3191 r180 top
C170 "GRM188R71H392KA01D" 0603L 1747.5,3265 r90 top
C171 "C0603C225K9PACTU" 0603L 6959.91,1961.65 r180 top
C172 "C0603C225K9PACTU" 0603L 6904.91,2009.65 r180 top
C173 "C0603C225K9PACTU" 0603L 6849.91,1961.65 r180 top
C174 "C0603C225K9PACTU" 0603L 6819.91,1887.65 r270 top
C175 "C0603C225K9PACTU" 0603L 6771.91,1838.65 r270 top
C176 "C0603C225K9PACTU" 0603L 6819.91,1783.65 r270 top
C177 "C0603C225K9PACTU" 0603L 6771.91,1728.65 r270 top
C178 "C0603C225K9PACTU" 0603L 6819.91,1673.65 r270 top
C179 "C0603C225K9PACTU" 0603L 6771.91,1618.65 r270 top
C180 "C0603C225K9PACTU" 0603L 6819.91,1563.65 r270 top
C181 "C0603C225K9PACTU" 0603L 6771.91,1508.65 r270 top
C182 "C0603C225K9PACTU" 0603L 6758.42,1433 r180 top
C183 "C0603C225K9PACTU" 0603L 6903.97,1950.65 r0 bottom
C184 "C0603C225K9PACTU" 0603L 7178.97,1998.65 r0 bottom
C185 "C0603C225K9PACTU" 0603L 6828.41,1751.1 r90 bottom
C186 "C0603C225K9PACTU" 0603L 7233.97,1950.65 r0 bottom
C187 "C0603C225K9PACTU" 0603L 6958.97,1998.65 r0 bottom
C188 "C0603C225K9PACTU" 0603L 6780.41,1806.1 r90 bottom
C189 "C0603C225K9PACTU" 0603L 7288.97,1998.65 r0 bottom
C190 "C0603C225K9PACTU" 0603L 7013.97,1950.65 r0 bottom
C191 "C0603C225K9PACTU" 0603L 6828.41,1861.1 r90 bottom
C192 "C0603C225K9PACTU" 0603L 7364.41,2026.21 r90 bottom
C193 "C0603C225K9PACTU" 0603L 7068.97,1998.65 r0 bottom
C194 "C0603C225K9PACTU" 0603L 6780.41,1916.1 r90 bottom
C196 "C1608X5R0J225M" 0603L 4701.42,3624.44 r270 bottom
C197 "C1608X5R0J225M" 0603L 6799.42,3630.44 r270 bottom
C200 "C1608X7R1C104K" 0603L 442,4083 r270 top
C201 "C1608X7R1C105K" 0603L 7074,4095 r0 top
C202 "C1608X7R1C105K" 0603L 7360,4304 r180 top
C203 "C1608X7R1C105K" 0603L 7023,4534 r0 top
C204 "GRM188R71C103KA01D" 0603L 7200,4535 r270 top
C205 "GRM188R71E103KA01D" 0603L 7362.42,517 r270 top
C207 "C3216X7R2A105M" 1206L 4735.42,3079.85 r90 top
C208 "EMK212BJ475KG-T" 0805_HV 4865.92,2904 r180 bottom
C209 "C3216X7R2A105M" 1206L 6398.42,2659 r0 top
C210 "EMK212BJ475KG-T" 0805_HV 6534.85,2467.98 r180 bottom
C214 "C1608X7R1C105K" 0603L 7152,4535.56 r270 top
C215 "GRM32ER72A105KA01L" 1210L 4537.92,3386 r0 top
C216 "GRM32ER72A105KA01L" 1210L 6644.42,3298 r270 top
C217 "GRM188R71C103KA01D" 0603L 4822.42,3496.44 r270 top
C218 "GRM188R71C103KA01D" 0603L 6895.92,3447 r270 top
C219 "C0805C225K4RACTU" 0805_HV 4377.42,3510 r0 bottom
C220 "C0805C225K4RACTU" 0805_HV 4528.42,3848 r0 bottom
C221 "C0805C225K4RACTU" 0805_HV 6582.42,3660 r270 bottom
C222 "C0805C225K4RACTU" 0805_HV 6635.42,3893 r0 bottom
C224 "GRM188R71C103KA01D" 0603L 7292,4499.56 r270 top
C225 "06035A470JAT2A" 0603L 4314.42,4009 r0 bottom
C226 "06035A470JAT2A" 0603L 6358.86,4012 r0 bottom
C227 "C1608X7R1C105K" 0603L 7340,4500 r270 top
C228 "C0603C104K8RACTU" 0603L 7251.42,1048 r0 top
C229 "C1608X7R1C104K" 0603L 2255,3034 r0 bottom
C230 "C1608X7R1C104K" 0603L 4377.42,3834 r0 top
C231 "C1608X7R1C104K" 0603L 6485.42,3842 r0 top
C232 "C1608X7R1E473K" 0603L 4748.98,3459 r180 top
C233 "C1608X7R1E473K" 0603L 4256.42,3947 r90 top
C234 "C1608X7R1E473K" 0603L 6847.92,3447 r90 top
C235 "C1608X7R1E473K" 0603L 6366.42,4009.18 r270 top
C236 "C1608X7R1C105K" 0603L 7103,1018.56 r90 bottom
C237 "C1608X7R1C105K" 0603L 7152.07,816.28 r270 top
C238 "C0603C100J5GACTU" 0603L 758.5,1424.8 r180 top
C239 "C1608X5R1C105K" 0603L 2462.42,2164 r90 bottom
C240 "C1608X5R1C105K" 0603L 2616.42,2037.44 r90 bottom
C241 "GRM188R71C103KA01D" 0603L 6922.44,4535 r0 top
C242 "C1608X7R1C105K" 0603L 6922.44,4487 r0 top
C243 "GRM188R71C103KA01D" 0603L 7360.56,4208 r180 top
C244 "C1608X7R1C105K" 0603L 7360.56,4256 r180 top
C248 "293D476X0010C" 6032-28 7307.42,950 r0 top
C249 "C1608X7R1C105K" 0603L 7285.42,491 r0 top
C250 "C1608X7R1C105K" 0603L 7425.42,737.56 r90 top
C251 "C1608C0G1H222J" 0603L 6987.42,1213.44 r180 top
C_Vstack1 "HMK212B7104KG-T" 0805_HV 4933.42,3069 r270 bottom
C_Vstack2 "HMK212B7104KG-T" 0805_HV 6599.42,2644 r270 bottom
CAN_POWER "961103-6404-AR" "1X3 100MIL PITCH" 294,1534 r90 top
CEXT1 "HMK212B7104KG-T" 0805_HV 4835.42,3254 r0 bottom
CEXT2 "HMK212B7104KG-T" 0805_HV 4613.42,3137 r90 bottom
CEXT3 "HMK212B7104KG-T" 0805_HV 6409,2666 r270 bottom
CEXT4 "HMK212B7104KG-T" 0805_HV 6202,2689 r90 bottom
D1 "MBRS230LT3G" SMB#1 5425,4358 r0 bottom
D2 "BAV99S" SOT-363 6279,2642 r0 bottom
D3 "3SMBJ5936B-TP" SMB#1 2150.99,2650 r0 top
D4 "PGB0010603MR" 0603L 491,3873 r270 top
D5 "BZX84C15LT1G" SOT-23 5971.6,2027.4 r180 top
D6 "PGB0010603MR" 0603L 490,4083 r90 top
D7 "BAV99S" SOT-363 4710,3112 r0 bottom
D8 "MBRS230LT3G" SMB#1 5081.01,4358 r180 bottom
D9 "PGB0010603MR" 0603L 443,3873.44 r270 top
D10 "CMHZ4702" SOD-123#1 1652.47,1463 r180 top
D11 "1N4148W-7-F" SOD-123#1 2033,1398 r180 top
D12 "1N4148W-7-F" SOD-123#1 2174,1333 r90 top
D13 "BAT41ZFILM" SOD-123#2 5003.88,3259 r0 bottom
D14 "BAT41ZFILM" SOD-123#2 6773.42,2669 r270 bottom
D15 "MMBD1504A" MF03A_L 6245.63,962.4 r180 bottom
D16 "BZX84C6V2LT1G" MF03A_L 4183.37,3115 r180 top
D17 "B120-13-F" SMA 4472.42,4329.26 r270 bottom
D18 "RS1MB-13-F" SMB#1 6080.57,863.06 r180 top
D19 "BZX84C6V2LT1G" MF03A_L 6278.63,3119.6 r180 top
D20 "B120-13-F" SMA 6485.42,4279 r270 bottom
D21 "BAT54WS-7-F" sod-323 1699.24,2565 r270 bottom
D22 "RS1MB-13-F" SMB#1 6080,1033 r180 top
D23 "B180-13-F" SMA 2077.68,1849 r0 bottom
D24 "MMBD1504A" MF03A_L 6086.88,1001.17 r90 bottom
D25 "1N4148W-7-F" SOD-123#1 2188.42,2462.53 r90 top
D26 "B180-13-F" SMA 1911,1899.26 r270 top
D27 "1N4148W-7-F" SOD-123#1 1505.53,3179 r0 top
D28 "B180-13-F" SMA 2114.1,2120.5 r270 top
D29 "DFLZ5V6-7" POWERDI123 3856.42,1342.8 r270 bottom
D30 "DFLZ5V6-7" POWERDI123 4458.42,1342.8 r270 bottom
D31 "DFLZ5V6-7" POWERDI123 5185.42,1342.8 r270 bottom
D32 "DFLZ5V6-7" POWERDI123 3719.42,1342.8 r270 bottom
D33 "DFLZ5V6-7" POWERDI123 4349.42,1342.8 r270 bottom
D34 "DFLZ5V6-7" POWERDI123 4979.42,1342.8 r270 bottom
D35 "DFLZ5V6-7" POWERDI123 3508.42,1342.8 r270 bottom
D36 "DFLZ5V6-7" POWERDI123 4840.42,1342.8 r270 bottom
D37 "DFLZ5V6-7" POWERDI123 4211.42,1342.8 r270 bottom
D38 "DFLZ5V6-7" POWERDI123 4703.42,1342.8 r270 bottom
D39 "DFLZ5V6-7" POWERDI123 3393.42,1342.8 r270 bottom
D40 "DFLZ5V6-7" POWERDI123 4103.42,1342.8 r270 bottom
D41 "DFLZ5V6-7" POWERDI123 4566.42,1342.8 r270 bottom
D42 "SMAJ64A" SMA 5404.42,1234.26 r270 bottom
D43 "DFLZ5V6-7" POWERDI123 3995.42,1342.8 r270 bottom
D44 "MMBD1504A" MF03A_M 6318,1125 r0 bottom
D45 "CMHZ4702" SOD-123#1 2339,3122.53 r90 top
D46 "HSMG-C150" HSMG-xxx 1007,4294.9 r270 top
D48 "HSMH-C150" HSMH-xxx 876,4283.9 r270 top
D49 "MMBD1504A" MF03A_L 6071.77,862 r180 bottom
D50 "1N4148W-7-F" SOD-123#1 1826.53,1398 r0 top
D51 "CMHZ4702" SOD-123#1 1446,1553 r180 top
D53 "ESD5B5.0ST1G" "SOD523 TVS" 6340,1810 r90 bottom
D54 "ESD5B5.0ST1G" "SOD523 TVS" 6404,1810 r90 bottom
D55 "ESD5B5.0ST1G" "SOD523 TVS" 6602.42,1352.44 r90 bottom
D56 "ESD5B5.0ST1G" "SOD523 TVS" 6535.42,1351.56 r90 bottom
D62 "1SMB5949BT3G" SMB#2 3965.99,4130 r0 top
D63 "1SMB5949BT3G" SMB#2 6095,4140 r0 top
D64 "BAT54WS-7-F" SOD-323 1532,3044 r180 top
Dclamp1 "1N5819HW-7-F" SOD-123#2 3305.51,3234 r180 top
Dclamp2 "1N5819HW-7-F" SOD-123#2 5497.95,3219 r180 top
F1 "SSQ 8" SSQ8A 5467.42,1481 r270 top
F2 "SSQ 8" SSQ8A 5325.42,1481 r270 top
F3 "SSQ 8" SSQ8A 5138.42,1529 r270 top
F4 "SSQ 8" SSQ8A 4996.42,1529 r270 top
F5 "SSQ 8" SSQ8A 4854.42,1529 r270 top
F6 "SSQ 8" SSQ8A 4712.42,1327 r90 top
F7 "SSQ 8" SSQ8A 4570.42,1529 r270 top
F8 "SSQ 12" SSQ8A 4428.42,1329 r90 top
F9 "SSQ 8" SSQ8A 4286.42,1529 r270 top
F10 "SSQ 8" SSQ8A 4143.42,1529 r270 top
F11 "SSQ 8" SSQ8A 4001.42,1529 r270 top
F12 "SSQ 8" SSQ8A 3859.42,1529 r270 top
F13 "SSQ 8" SSQ8A 3717.42,1529 r270 top
F14 "SSQ 8" SSQ8A 3510.19,1480 r270 top
F15 "SSQ 8" SSQ8A 3288.19,1480 r270 top
F16 "0437002.WR" 1206M 748,4115.98 r90 top
F17 "0437002.WR" 1206M 2030,1522 r180 top
F18 "0459002.UR" 0459002.UR 2174,1075 r270 top
F19 "0459002.UR" 0459002.UR 1987,1075 r270 top
J1 "TSW-107-07-G-S" TSW-107-XX-XXX-S 3706,4863 r180 top
J2 "5767096-8" 5767096-8 6373,5003 r180 top
J3 "TC2050-IDC-NL" TC2050-IDC-NL-10 7197,4928 r180 top
J4 "5767096-8" 5767096-8 1158,4889 r180 top
J5 "DM3BT-DSF-PEJS" DM3BT-DSF-PEJS 714,3368 r90 bottom
J7 "AWHW20-G-SMD-R" "2X10 SHROUDED SURFACE MOUNT HDR" 2211,4716 r0 top
L1 "MI0603M121R-10" 0603 827,511.5 r270 bottom
L3 "MI0603M121R-10" 0603 1868,1682 r270 top
L4 "MI0603M121R-10" 0603 7567,3145.5 r270 bottom
L5 "7443320680" "WURTH 7443320680" 3401.92,2885 r0 top
L6 "MI0603M121R-10" 0603 7068,2713 r90 bottom
L7 "7443320680" "WURTH 7443320680" 5635.3,2896 r0 top
L8 "MI0603M121R-10" 0603 4820.5,4825 r180 bottom
L9 "MI0603M121R-10" 0603 7173.5,2577 r0 bottom
L10 "CDRH6D28NP-100NC" CDRH6D28 5603.54,4620 r0 bottom
L11 "CDRH6D28NP-5R0NC" CDRH6D28 4902.46,4618 r0 bottom
Logo1 "Texas Instruments" TI_Logo_CopperSolderMask_1p1_x_p275 590,3135 r0 top
MNT1 "Used in BOM report" "4-40 SCREW"#1 7600,200 r0 top locked
MNT2 "Used in BOM report" "4-40 SCREW"#1 7600,5100 r90 top locked
MNT3 "Used in BOM report" "4-40 SCREW"#1 200,5100 r180 top locked
MNT4 "Used in BOM report" "4-40 SCREW"#1 200,1020 r270 top
MNT5 "Used in BOM report" "4-40 SCREW"#2 2674.42,2862 r0 top
MNT6 "Used in BOM report" "4-40 SCREW"#1 508,4889 r0 top
MNT7 "Used in BOM report" "4-40 SCREW"#1 1808,4889 r0 top
MNT8 "Used in BOM report" "4-40 SCREW"#2 1098,2835 r0 top
NT3 "" 0805_Net_Tie#1 5605,695 r180 top net-tie
NT4 "" 0805_Net_Tie#2 5500,664.49 r90 top net-tie
NT6 "" 0805_Net_Tie#1 5506,531.53 r90 top net-tie
P1 "UX60A-MB-5ST" UX60A-MB-5ST 12.95,3945.35 r270 top
P2 "1452625-1" 1452625-1 2077.4,613.57 r270 top
P3 "A00-216-262-450" A00-216-262-450 738,682 r0 top
PING_IN1 "1565749-1" 1565749-1 6265.53,519.58 r270 top
PING_OFF "961102-6404-AR" "1X2 100MIL PITCH" 6243,1281 r180 top
PING_OUT1 "1376350-2" 1376350-2 6865.46,618.01 r270 top
Q1 "SI7938DP" "POWERPAK SO-8 -Dual"#1 4155.42,2445.67 r270 top
Q2 "SI7938DP" "POWERPAK SO-8 -Dual"#1 3981.42,2983 r180 top
Q3 "SI7938DP" "POWERPAK SO-8 -Dual"#1 4125.42,2080.67 r270 top
Q4 "SI7938DP" "POWERPAK SO-8 -Dual"#1 4187.42,2959 r180 bottom
Q5 "SI7938DP" "POWERPAK SO-8 -Dual"#1 3889.42,2454.67 r270 top
Q6 "SI7938DP" "POWERPAK SO-8 -Dual"#1 3695.42,2080.67 r270 top
Q7 "SI7938DP" "POWERPAK SO-8 -Dual"#1 3486.42,2455.67 r270 top
Q8 "SI7938DP" "POWERPAK SO-8 -Dual"#1 3266.42,2080.67 r270 top
Q9 "SI7938DP" "POWERPAK SO-8 -Dual"#1 3055.42,2455.67 r270 top
Q10 "SI7938DP" "POWERPAK SO-8 -Dual"#1 2892.42,2080.67 r270 top
Q11 "2N7002W-7-F" SOT-323 6767.5,1386 r0 bottom
Q12 "SI2337DS-T1-E3" MF03A_N 1631,1340.34 r270 top
Q13 "2N7002W-7-F" SOT-323 1611.5,1725 r0 top
Q14 "SI7938DP" "POWERPAK SO-8 -Dual"#2 5734.5,2072.25 r270 top
Q15 "SI7938DP" "POWERPAK SO-8 -Dual"#1 6079.94,2984.24 r180 top
Q16 "SI7938DP" "POWERPAK SO-8 -Dual"#2 5481,2394.67 r270 top
Q17 "SI7938DP" "POWERPAK SO-8 -Dual"#1 6284.42,2959 r180 bottom
Q18 "SI7938DP" "POWERPAK SO-8 -Dual"#2 5329,2030.67 r270 top
Q19 "SI7938DP" "POWERPAK SO-8 -Dual"#2 5098,2394.67 r270 top
Q20 "SI7938DP" "POWERPAK SO-8 -Dual"#2 4948,2031 r270 top
Q21 "SI7938DP" "POWERPAK SO-8 -Dual"#2 4758,2394.67 r270 top
Q22 "SI7938DP" "POWERPAK SO-8 -Dual"#2 4578,2030.32 r270 top
Q23 "SI7938DP" "POWERPAK SO-8 -Dual"#2 4501,2438.67 r90 top
Q24 "2N7002W-7-F" SOT-323 1443,1723.5 r90 top
Q25 "BC856B-7-F" MF03A_M 5686.6,1204.37 r90 bottom
Q26 "SI7439DP-T1-E3" PowerPAK_SO-8 3898.5,4333 r180 top
Q27 "RJK0330DPB" LFPAK 3947.12,3633.53 r90 top
Q28 "SI7846DP-T1-E3" PowerPAK_SO-8 3898.5,3928 r180 top
Q29 "RJK0330DPB" LFPAK 3947.12,3389.53 r90 top
Q31 "RJK0330DPB" LFPAK 6071.84,3625.5 r90 top
Q32 "SI7439DP-T1-E3" PowerPAK_SO-8 6039.5,4334 r180 top
Q33 "SI7846DP-T1-E3" PowerPAK_SO-8 6032.5,3927 r180 top
Q34 "RJK0330DPB" LFPAK 6072.92,3380 r90 top
Q35 "2N7002W-7-F" SOT-323 2382,3283 r0 top
Q36 "SI7898DP-E3" PowerPAK_SO-8 2421.92,2500.39 r270 top
Q37 "SI2323DS" SOT-23 1362,2820 r90 bottom
Q38 "2N7002W-7-F" SOT-323 1557,2683.5 r90 bottom
Q40 "ZXMP10A13FTA" MF03A_N 6801.42,1222.66 r90 top
Q41 "2N7002W-7-F" SOT-323 7303.42,2068.5 r90 top
Q43 "BSS123W-7-F" SOT-323 1576,2375 r270 bottom
Q44 "SI2337DS-T1-E3" MF03A_N 2138.75,3168 r180 top
Q45 "2N7002W-7-F" SOT-323 467.41,2610.5 r90 top
Q46 "SUM110P08-11L" DDPAK 5950.42,1573.51 r270 top
Q47 "2N7002W-7-F" SOT-323 6234.42,1940 r180 top
Q48 "BC856B-7-F" SOT-23 5914.4,1341.4 r0 bottom
Q49 "BC846BLT1G" SOT-23 5761.6,944.6 r180 bottom
Q52 "SI2337DS-T1-E3" SOT-23 6635.4,1113.6 r0 bottom
Q53 "FMMT596TA" SOT-23 6515.4,962.6 r0 bottom
Q54 "FMMT596TA" SOT-23 6296.6,1634.4 r90 bottom
Q55 "FMMT596TA" SOT-23 5951.4,1184.4 r90 bottom
Q56 "FMMT495TA" SOT-23 6084,1141 r270 bottom
Q57 "FMMT596TA" SOT-23 6246.4,1441 r180 bottom
R1 "CRCW0603732RFKEA" 0603L 7152.91,2083.65 r270 top
R2 "CRCW0603732RFKEA" 0603L 7096.91,2083.65 r270 top
R3 "CRCW0603732RFKEA" 0603L 7042.91,2083.65 r270 top
R4 "CRCW0603732RFKEA" 0603L 6986.91,2083.65 r270 top
R5 "CRCW0603732RFKEA" 0603L 6932.91,2083.65 r270 top
R6 "CRCW0603732RFKEA" 0603L 6791.41,2019.65 r0 top
R7 "CRCW0603732RFKEA" 0603L 6744.41,1971.65 r0 top
R8 "CRCW0603732RFKEA" 0603L 6744.85,1921.65 r0 top
R9 "CRCW0603732RFKEA" 0603L 6696.91,1810.65 r0 top
R10 "CRCW0603732RFKEA" 0603L 6696.91,1755.65 r0 top
R11 "CRCW0603732RFKEA" 0603L 6696.91,1700.65 r0 top
R12 "CRCW0603732RFKEA" 0603L 6696.91,1645.65 r0 top
R13 "CRCW0603732RFKEA" 0603L 6696.91,1590.65 r0 top
R14 "CRCW0603732RFKEA" 0603L 6696.91,1535.65 r0 top
R15 "CRCW0603732RFKEA" 0603L 6696.91,1480.65 r0 top
R16 "CRCW0603100RFKEA" 0603L 7262.41,1294.65 r180 top
R17 "CRCW060360K4FKEA" 0603L 6760.91,1327.65 r0 top
R18 "CRCW06031K00FKEA" 0603L 6757.91,1384.65 r0 top
R19 "ERJ-3EKF2701V" 0603L 7060.91,1342.65 r90 top
R20 "CRCW06030000Z0EA" 0603L 7309.42,1147 r180 top
R21 "CRCW06030000Z0EA" 0603L 902.56,1831 r180 bottom
R22 "CRCW060349R9FKEA" 0603L 6624.32,4909 r0 bottom
R23 "CRCW0603499RFKEA" 0603L 4662.42,3101.5 r270 top
R24 "CRCW060349k9FKEA" 0603L 6698.44,1305 r180 bottom
R25 "CRCW06030000Z0EA" 0603L 663,1785.56 r270 top
R26 "CRCW060360R4FKEA" 0603L 881,1284.56 r270 bottom
R27 "CRCW06030000Z0EA" 0603L 763,2533 r270 bottom
R28 "CRCW06030000Z0EA" 0603L 813,1785 r270 top
R29 "CRCW0603499RFKEA" 0603L 6369.42,2733 r180 top
R30 "ERJ-3EKF2701V" 0603L 7177.42,1074.44 r270 top
R31 "CRCW06030000Z0EA" 0603L 7112.41,600.65 r180 top
R32 "CRCW06030000Z0EA" 0603L 7132.42,731 r180 top
R33 "CRCW06030000Z0EA" 0603L 7132.41,682.65 r180 top
R34 "CRCW06030000Z0EA" 0603L 7284.42,544 r180 top
R35 "CRCW0603787KFKEA" 0603L 6901.42,1295.5 r270 top
R36 "CRCW060349R9FKEA" 0603L 2070,3371.56 r90 bottom
R37 "CRCW0603200KJNEA" 0603L 1615,1540 r180 top
R38 "CRCW06030000Z0EA" 0603L 713,2533 r270 bottom
R39 "CRCW060349R9FKEA" 0603L 6624.32,4813 r0 bottom
R40 "CRCW06030000Z0EA" 0603L 881,1105.56 r270 bottom
R41 "CRCW06030000Z0EA" 0603L 602,1104.56 r270 bottom
R42 "RC0603FR-0710RL" 0603L 6697.44,1523 r180 bottom
R43 "RC0603FR-0710RL" 0603L 6698,1257 r180 bottom
R44 "CRCW060347K0JNEA" 0603L 1352.56,2715 r0 bottom
R45 "RC0603FR-0710RL" 0603L 6877,1392 r180 bottom
R46 "CRCW060347K0JNEA" 0603L 6877.44,1335 r180 bottom
R47 "CRCW06031K00FKEA" 0603L 890.44,4438 r0 top
R48 "CRCW06030000Z0EA" 0603L 4348.98,4306 r180 bottom
R49 "CRCW06030000Z0EA" 0603L 6363.98,4317 r180 bottom
R50 "CRCW06030000Z0EA" 0603L 7455.98,1452 r180 top
R51 "CRCW06031K00FKEA" 0603L 5869.53,844.58 r90 bottom
R52 "CRCW06031K00FKEA" 0603L 990.44,4438 r180 top
R53 "RT0603BRD0710KL" 0603L 6847.42,3630.44 r270 bottom
R54 "RT0603BRD0710KL" 0603L 4750.42,3624.88 r270 bottom
R55 "RC0603FR-0710RL" 0603L 5917,844.56 r90 bottom
R56 "CRCW06030000Z0EA" 0603L 2319.56,3847 r180 bottom
R57 "CRCW060366K5FKEA" 0603L 7454.98,1500 r0 top
R58 "CRCW060349R9FKEA" 0603L 1462,3024.44 r270 top
R59 "CRCW06031K00FKEA" 0603L 5902,835.5 r270 top
R60 "CRCW06031K00FKEA" 0603L 5898,1005.44 r270 top
R61 "RC0603FR-079K1L" 0603L 1342.5,4089 r180 bottom
R62 "CRCW06030000Z0EA" 0603L 565.44,1945 r180 bottom
R63 "CRCW060310R0FKEA" 0603L 5167,5025.5 r270 bottom
R64 "CRCW060349k9FKEA" 0603L 5411.56,4908 r180 bottom
R65 "CRCW0603100kFKEA" 0603L 1186.56,4151 r0 bottom
R66 "RT0603DRE07100KL" 0603L 597,1415 r270 bottom
R67 "RT0603DRE07100KL" 0603L 634.56,2629 r180 top
R68 "RC0603FR-0710RL" 0603L 2905.42,1223.5 r270 bottom
R69 "RC0603FR-0710RL" 0603L 2835.42,1223.5 r270 bottom
R70 "RC0603FR-0710RL" 0603L 2765.42,1223.5 r270 bottom
R71 "RC0603FR-0710RL" 0603L 2695.42,1223.5 r270 bottom
R72 "RC0603FR-0710RL" 0603L 2419.42,1226.44 r270 bottom
R73 "RC0603FR-0710RL" 0603L 2349.42,1226.44 r270 bottom
R74 "RC0603FR-0710RL" 0603L 2279.42,1226.44 r270 bottom
R75 "RC0603FR-0710RL" 0603L 2209.42,1226.44 r270 bottom
R76 "CRCW060333R0JNEA" 0603L 7381,3960 r270 top
R77 "CRCW060310k0FKEA" 0603L 2711,4664.56 r270 bottom
R78 "CRCW060310k0FKEA" 0603L 3011,4664.56 r270 bottom
R79 "CRCW060310k0FKEA" 0603L 3111,4664.56 r270 bottom
R80 "CRCW060333R0JNEA" 0603L 7326,3960.38 r270 top
R81 "CRCW06030000Z0EA" 0603L 907,4823 r270 bottom
R82 "CRCW060349R9FKEA" 0603L 6849.5,4108 r180 top
R83 "CRCW0603249KFKEA" 0603L 2056,1293 r0 top
R84 "CRCW06030000Z0EA" 0603L 859,4822.56 r270 bottom
R85 "CRCW06030000Z0EA" 0603L 6872.44,4050 r180 top
R86 "CRCW06030000Z0EA" 0603L 6873,3978 r180 top
R87 "CRCW06030000Z0EA" 0603L 6529,4763.44 r270 bottom
R88 "CRCW060333R0JNEA" 0603L 1694.44,3642 r0 top
R89 "CRCW060310K0FKEA" 0603L 5766,1341.44 r90 bottom
R90 "CRCW04021K00FKED" 0402 7236,4736 r270 top
R91 "CRCW04021K00FKED" 0402 7442,4278.38 r90 top
R92 "CRCW06030000Z0EA" 0603L 7130,3961 r270 top
R93 "CRCW0603200KJNEA" 0603L 1407.56,2266 r0 bottom
R94 "RT0603DRE07100KL" 0603L 7129.64,3314.57 r270 bottom
R95 "CRCW06030000Z0EA" 0603L 618,1945 r180 top
R96 "CRCW0603316KFKEA" 0603L 7416.64,3205.57 r270 bottom
R97 "CRCW06030000Z0EA" 0603L 7178,3961 r270 top
R98 "RT0603DRE07100KL" 0603L 7416.64,3308.12 r90 bottom
R99 "CRCW06030000Z0EA" 0603L 7226,3961 r270 top
R100 "CRCW06030000Z0EA" 0603L 7183.42,491 r0 top
R101 "CRCW06030000Z0EA" 0603L 7274,3961 r270 top
R102 "CRCW06030000Z0EA" 0603L 7130,3960.44 r270 bottom
R103 "CRCW06030000Z0EA" 0603L 7178,3961 r270 bottom
R104 "CRCW06030000Z0EA" 0603L 2362.86,1908 r0 bottom
R105 "CRCW06030000Z0EA" 0603L 2463.97,1908 r0 bottom
R106 "CRCW0603732RFKEA" 0603L 6704.85,1668.65 r0 bottom
R107 "CRCW0603732RFKEA" 0603L 6704.85,1723.65 r0 bottom
R108 "CRCW0603732RFKEA" 0603L 6705.29,1777.65 r0 bottom
R109 "CRCW0603732RFKEA" 0603L 6705.29,1833.65 r0 bottom
R110 "CRCW0603732RFKEA" 0603L 6703.29,1888.65 r0 bottom
R111 "CRCW0603732RFKEA" 0603L 6705.29,1942.65 r0 bottom
R112 "CRCW0603732RFKEA" 0603L 6876.41,2026.21 r270 bottom
R113 "CRCW060349k9FKEA" 0603L 6815.42,1143.56 r270 bottom
R114 "CRCW0603732RFKEA" 0603L 6931.41,2076.21 r270 bottom
R115 "CRCW060349k9FKEA" 0603L 6900.42,1176.44 r90 bottom
R116 "CRCW0603732RFKEA" 0603L 6986.41,2076.21 r270 bottom
R117 "CRCW060349k9FKEA" 0603L 7088.42,1184.44 r90 bottom
R118 "CRCW0603732RFKEA" 0603L 7040.41,2076.21 r270 bottom
R119 "CRCW060349k9FKEA" 0603L 7136.42,1184.56 r90 bottom
R120 "CRCW0603732RFKEA" 0603L 7096.41,2076.21 r270 bottom
R121 "CRCW060349k9FKEA" 0603L 7286.56,1251 r180 bottom
R122 "CRCW0603732RFKEA" 0603L 7151.41,2076.21 r270 bottom
R123 "CRCW0603732RFKEA" 0603L 7206.41,2076.21 r270 bottom
R124 "CRCW0603732RFKEA" 0603L 7261.41,2076.21 r270 bottom
R125 "CRCW06030000Z0EA" 0603L 7448.42,1072.44 r90 top
R126 "CRCW0603133KFKEA" 0603L 7157.92,2173.99 r180 top
R127 "CRCW0603402KFKEA" 0603L 7292.98,2174 r180 top
R128 "CRCW060349k9FKEA" 0603L 7411.98,2172 r0 bottom
R129 "CRCW080510R0FKEA" 0805_HV 5294.42,1353 r90 bottom
R130 "CRCW0603732RFKEA" 0603L 7316.41,2076.21 r270 bottom
R131 "CRCW0603100RFKEA" 0603L 7431.41,1744.21 r270 bottom
R132 "RC0603JR-078K2L" 0603L 7512.42,1833.44 r90 bottom
R133 "CRCW060310K2FKEA" 0603L 7550.42,2195.44 r90 bottom
R134 "CRCW0603100RFKEA" 0603L 7412.42,1556.44 r270 bottom
R135 "CRCW060351K0JNEA" 0603L 7560.42,1933.56 r90 bottom
R136 "CRCW060310K7FKEA" 0603L 7502.42,2195.44 r90 bottom
R137 "CRCW0603200KJNEA" 0603L 7303.42,1991 r180 top
R138 "CRCW060354K9FKEA" 0603L 1679.44,2635 r0 bottom
R139 "CRCW060317K8FKEA" 0603L 7351.92,2323 r180 bottom
R140 "CRCW060310K0FKEA" 0603L 7351.48,2394 r0 bottom
R141 "CRCW06030000Z0EA" 0603L 7226,3961 r270 bottom
R142 "CRCW06030000Z0EA" 0603L 7274,3961 r270 bottom
R143 "CRCW06030000Z0EA" 0603L 6906.42,989 r0 top
R144 "CRCW06030000Z0EA" 0603L 6906,941 r0 top
R145 "CRCW0603200KJNEA" 0603L 2246,3170 r90 top
R146 "CRCW060349R9FKEA" 0603L 7041,4096 r0 bottom
R147 "CRCW060349R9FKEA" 0603L 1297,3705 r90 bottom
R148 "CRCW0603442KFKEA" 0603L 2414,3085.56 r270 top
R149 "CRCW060349R9FKEA" 0603L 7382,4271.44 r270 bottom
R150 "CRCW0603174KFKEA" 0603L 1352.56,2660 r180 bottom
R151 "CRCW060310K0FKEA" 0603L 713,2551.56 r270 top
R152 "CRCW060326K7FKEA" 0603L 5050,4911 r0 bottom
R153 "CRCW06035K90FKEA" 0603L 5049.5,5053 r0 bottom
R154 "CRCW06030000Z0EA" 0603L 859,4954.44 r90 bottom
R155 "CRCW06030000Z0EA" 0603L 6995.44,846 r180 top
R156 "CRCW06030000Z0EA" 0603L 6995.44,894 r180 top
R157 "CRCW06030000Z0EA" 0603L 7240.31,962.35 r270 bottom
R158 "CRCW06030000Z0EA" 0603L 7192.31,961.79 r270 bottom
R159 "CRCW060310K0FKEA" 0603L 763,2551.56 r270 top
R160 "CRCW06030000Z0EA" 0603L 597,1571 r270 top
R161 "CRCW0603560RJNEA" 0603L 6606.98,1207 r180 bottom
R162 "CRCW0603560RJNEA" 0603L 6491.42,1209 r0 bottom
R163 "CRCW06030000Z0EA" 0603L 876,1571 r270 top
R164 "CRCW06030000Z0EA" 0603L 515.44,1945 r0 top
R165 "CRCW06030000Z0EA" 0603L 813,2551.56 r270 top
R166 "ERJ-1TYJ220U" 2512M 5644.42,1520.08 r90 top
R167 "CRCW0603100kFKEA" 0603L 5981.44,1940 r180 top
R168 "CRCW0603100kFKEA" 0603L 6128.42,1940 r0 top
R169 "CRCW0603100kFKEA" 0603L 6316.42,1941.56 r90 top
R170 "CRCW06030000Z0EA" 0603L 4281.42,3611 r0 top
R171 "CRCW06030000Z0EA" 0603L 4319.42,4479.56 r270 bottom
R172 "RT0603BRD0710KL" 0603L 4348.98,4554.44 r0 bottom
R173 "CRCW0603100kFKEA" 0603L 4207.42,3583.44 r90 top
R174 "WSL2010R0100FEA18" 2010M 4292.92,3398 r0 top
R175 "CRCW06030000Z0EA" 0603L 4256.42,3746 r270 top
R176 "CRCW0603442KFKEA" 0603L 1643,1618.56 r270 top
R177 "CRCW0603100kFKEA" 0603L 4256.42,3846.56 r270 top
R178 "CRCW06030000Z0EA" 0603L 4294.42,3543 r180 top
R179 "ERJ-L12KF33MU" 1812 4153.42,3950 r270 top
R180 "CRCW0603100kFKEA" 0603L 4239.92,3493 r180 top
R181 "CRCW0603560RJNEA" 0603L 6506,1629.44 r270 bottom
R182 "CRCW0603560RJNEA" 0603L 6431.42,1695 r0 bottom
R183 "CRCW060310K0FKEA" 0603L 5814,1341.44 r90 bottom
R184 "CRCW06031K10FKEA" 0603L 5917,955 r90 bottom
R185 "CRCW060310K0FKEA" 0603L 5869.56,954.44 r270 bottom
R186 "CRCW060347K0JNEA" 0603L 5724,1061.56 r270 bottom
R187 "CRCW06035K90FKEA" 0603L 5353,5057 r0 bottom
R188 "CRCW06030000Z0EA" 0603L 6398.42,3596 r0 top
R189 "CRCW06030000Z0EA" 0603L 6262.86,4465 r0 bottom
R190 "RT0603BRD0710KL" 0603L 6207.86,4516 r180 bottom
R191 "CRCW0603100kFKEA" 0603L 6307.42,3568.44 r90 top
R192 "WSL2010R0100FEA18" 2010M 6384.92,3397 r0 top
R193 "CRCW06030000Z0EA" 0603L 907,4954.44 r90 bottom
R194 "CRCW06030000Z0EA" 0603L 6361.42,3765 r270 top
R195 "CRCW0603100kFKEA" 0603L 6362.42,3865 r270 top
R196 "CRCW06030000Z0EA" 0603L 6389.86,3548.12 r180 top
R197 "ERJ-L12KF33MU" 1812 6260,3940 r270 top
R198 "CRCW0603100kFKEA" 0603L 6334.98,3495 r180 top
R199 "CRCW060349k9FKEA" 0603L 6949.42,1176.56 r270 bottom
R200 "CRCW06030000Z0EA" 0603L 6120,4939.44 r270 bottom
R201 "CRCW060320K0FKEA" 0603L 2919.42,1364.56 r90 bottom
R202 "CRCW060320K0FKEA" 0603L 2825.97,1489 r0 bottom
R203 "CRCW060320K0FKEA" 0603L 2628.42,1416.44 r90 bottom
R204 "CRCW060320K0FKEA" 0603L 2628.42,1521.44 r270 bottom
R205 "CRCW060320K0FKEA" 0603L 2449.42,1405.44 r90 bottom
R206 "CRCW060320K0FKEA" 0603L 2449.42,1508.44 r270 bottom
R207 "CRCW060320K0FKEA" 0603L 2266.42,1405.56 r90 bottom
R208 "CRCW060320K0FKEA" 0603L 2266.42,1508.44 r270 bottom
R209 "CRCW06030000Z0EA" 0603L 6072,4939.56 r270 bottom
R210 "CRCW0603910KJNEA" 0603L 1443,1846.5 r90 top
R211 "CRCW0603150KJNEA" 0603L 1521,1724.5 r270 top
R212 "CRCW1206100RFKEA" 1206L 1854,3068 r180 top
R213 "CRCW06030000Z0EA" 0603L 2160.86,2463 r180 bottom
R214 "CRCW08055K10JNEA" 0805_HV 2154.42,2090 r0 bottom
R215 "CRCW060349k9FKEA" 0603L 1443,1638 r0 top
R216 "RT0603DRE07100KL" 0603L 1472,2592.44 r270 bottom
R217 "CRCW120610R0FKEA" 1206L 2001.85,1714 r0 top
R218 "CRCW06030000Z0EA" 0603L 2363.42,1860 r0 top
R219 "CRCW060310K0FKEA" 0603L 1960,2876.44 r90 top
R220 "CRCW08055K10JNEA" 0805_HV 2376.42,1932 r180 top
R221 "CRCW0603100RFKEA" 0603L 1726.5,2803 r0 top
R222 "CRCW060375K0FKEA" 0603L 1827.44,2950 r180 top
R223 "RT0603DRE07100KL" 0603L 617,2551.56 r90 top
R224 "MCR25JZHFLR270" 1210M 2392.98,2789 r0 top
R225 "CRCW06030000Z0EA" 0603L 6070,5068.44 r90 bottom
R226 "CRCW0603115KFKEA" 0603L 1694.5,3265 r270 top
